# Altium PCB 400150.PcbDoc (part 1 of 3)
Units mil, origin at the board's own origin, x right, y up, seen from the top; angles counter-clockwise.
Board outline 4000 x 2500 mil, 4 copper layers (Top Layer, Mid-Layer 1, Mid-Layer 2, Bottom Layer), stack 62.293 mil thick; 200 components, 153 nets, 913 pads, 613 vias.
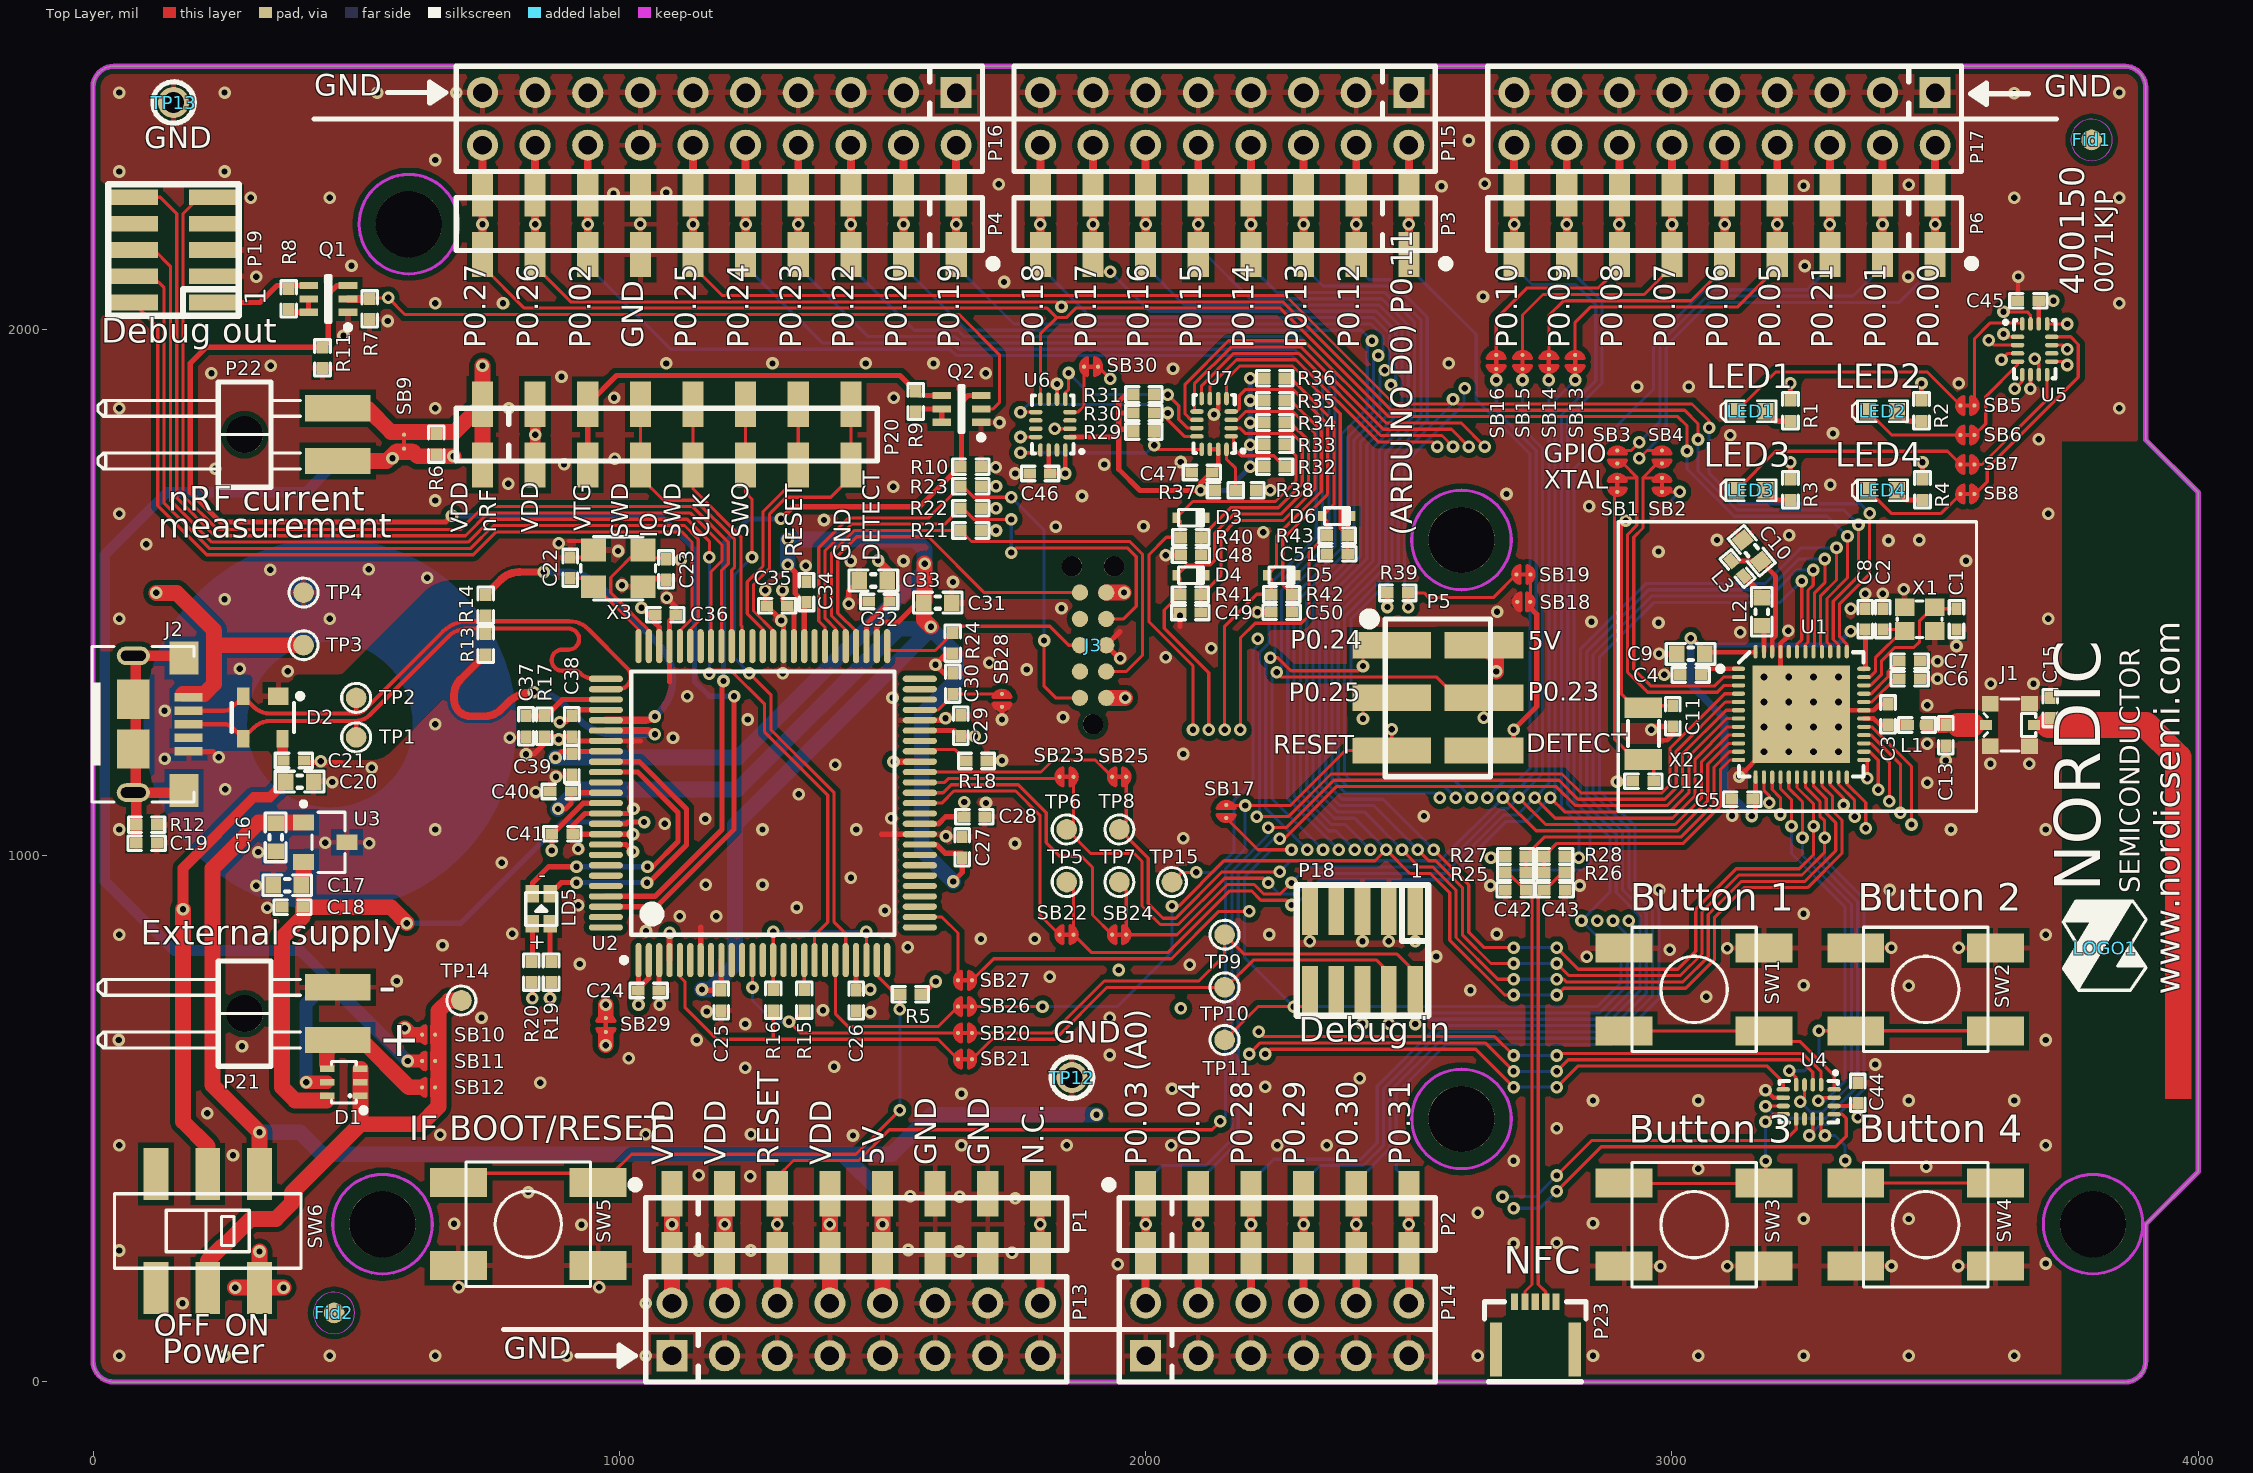
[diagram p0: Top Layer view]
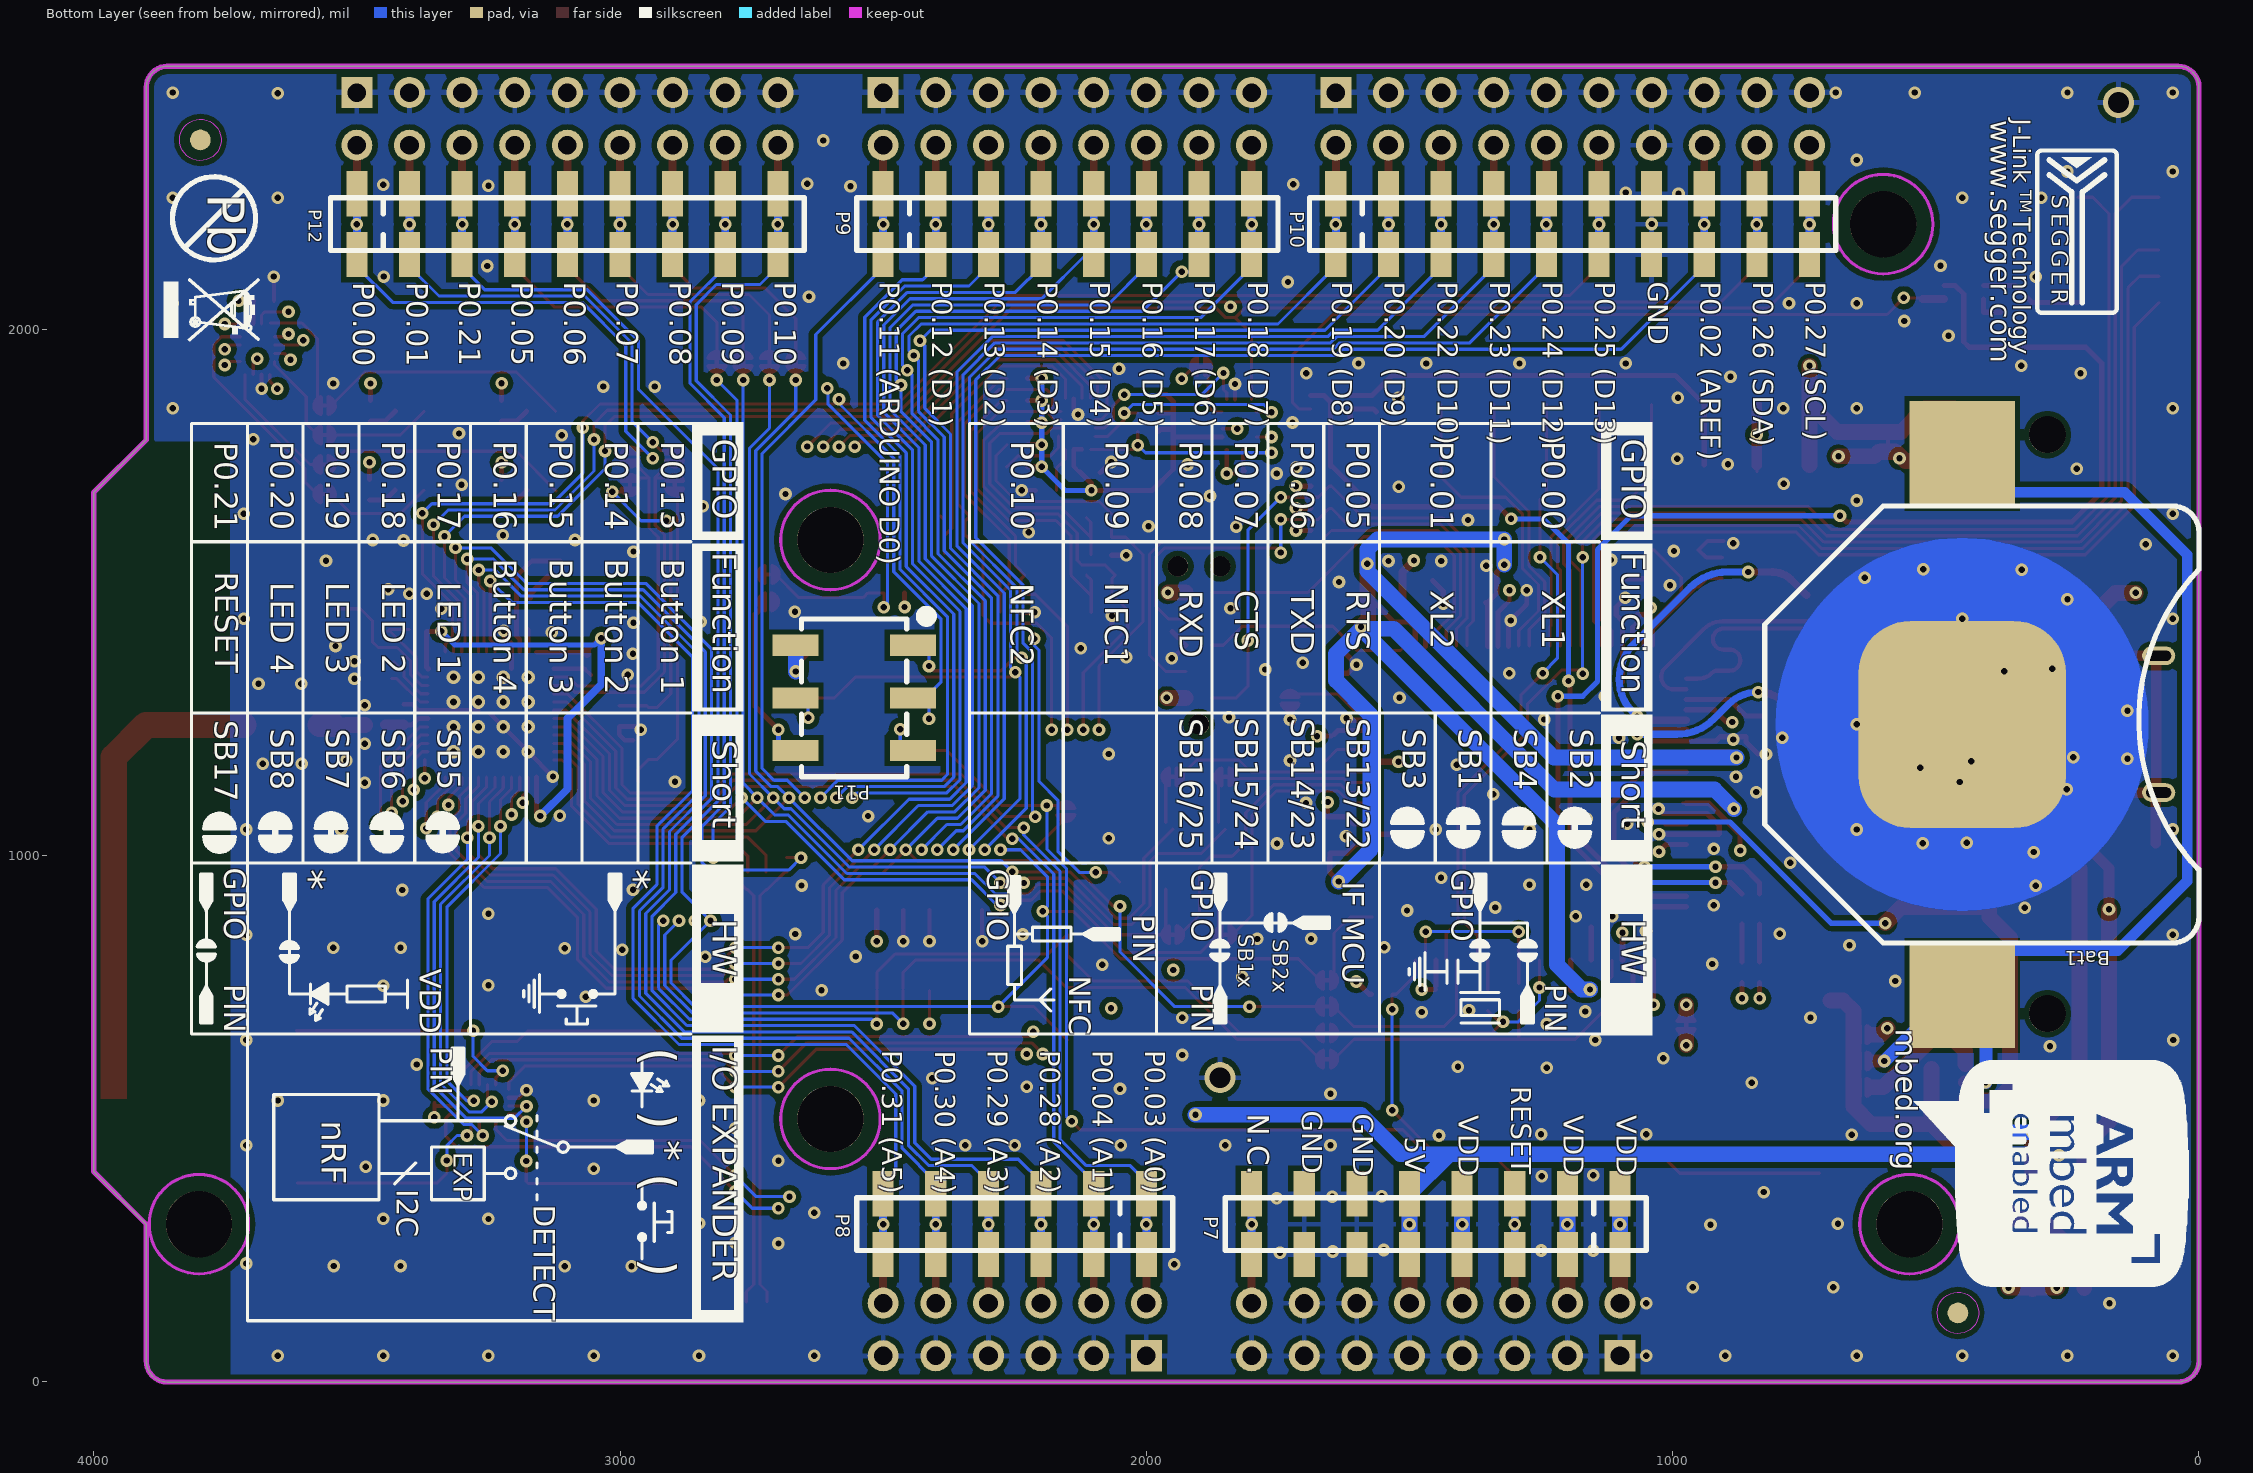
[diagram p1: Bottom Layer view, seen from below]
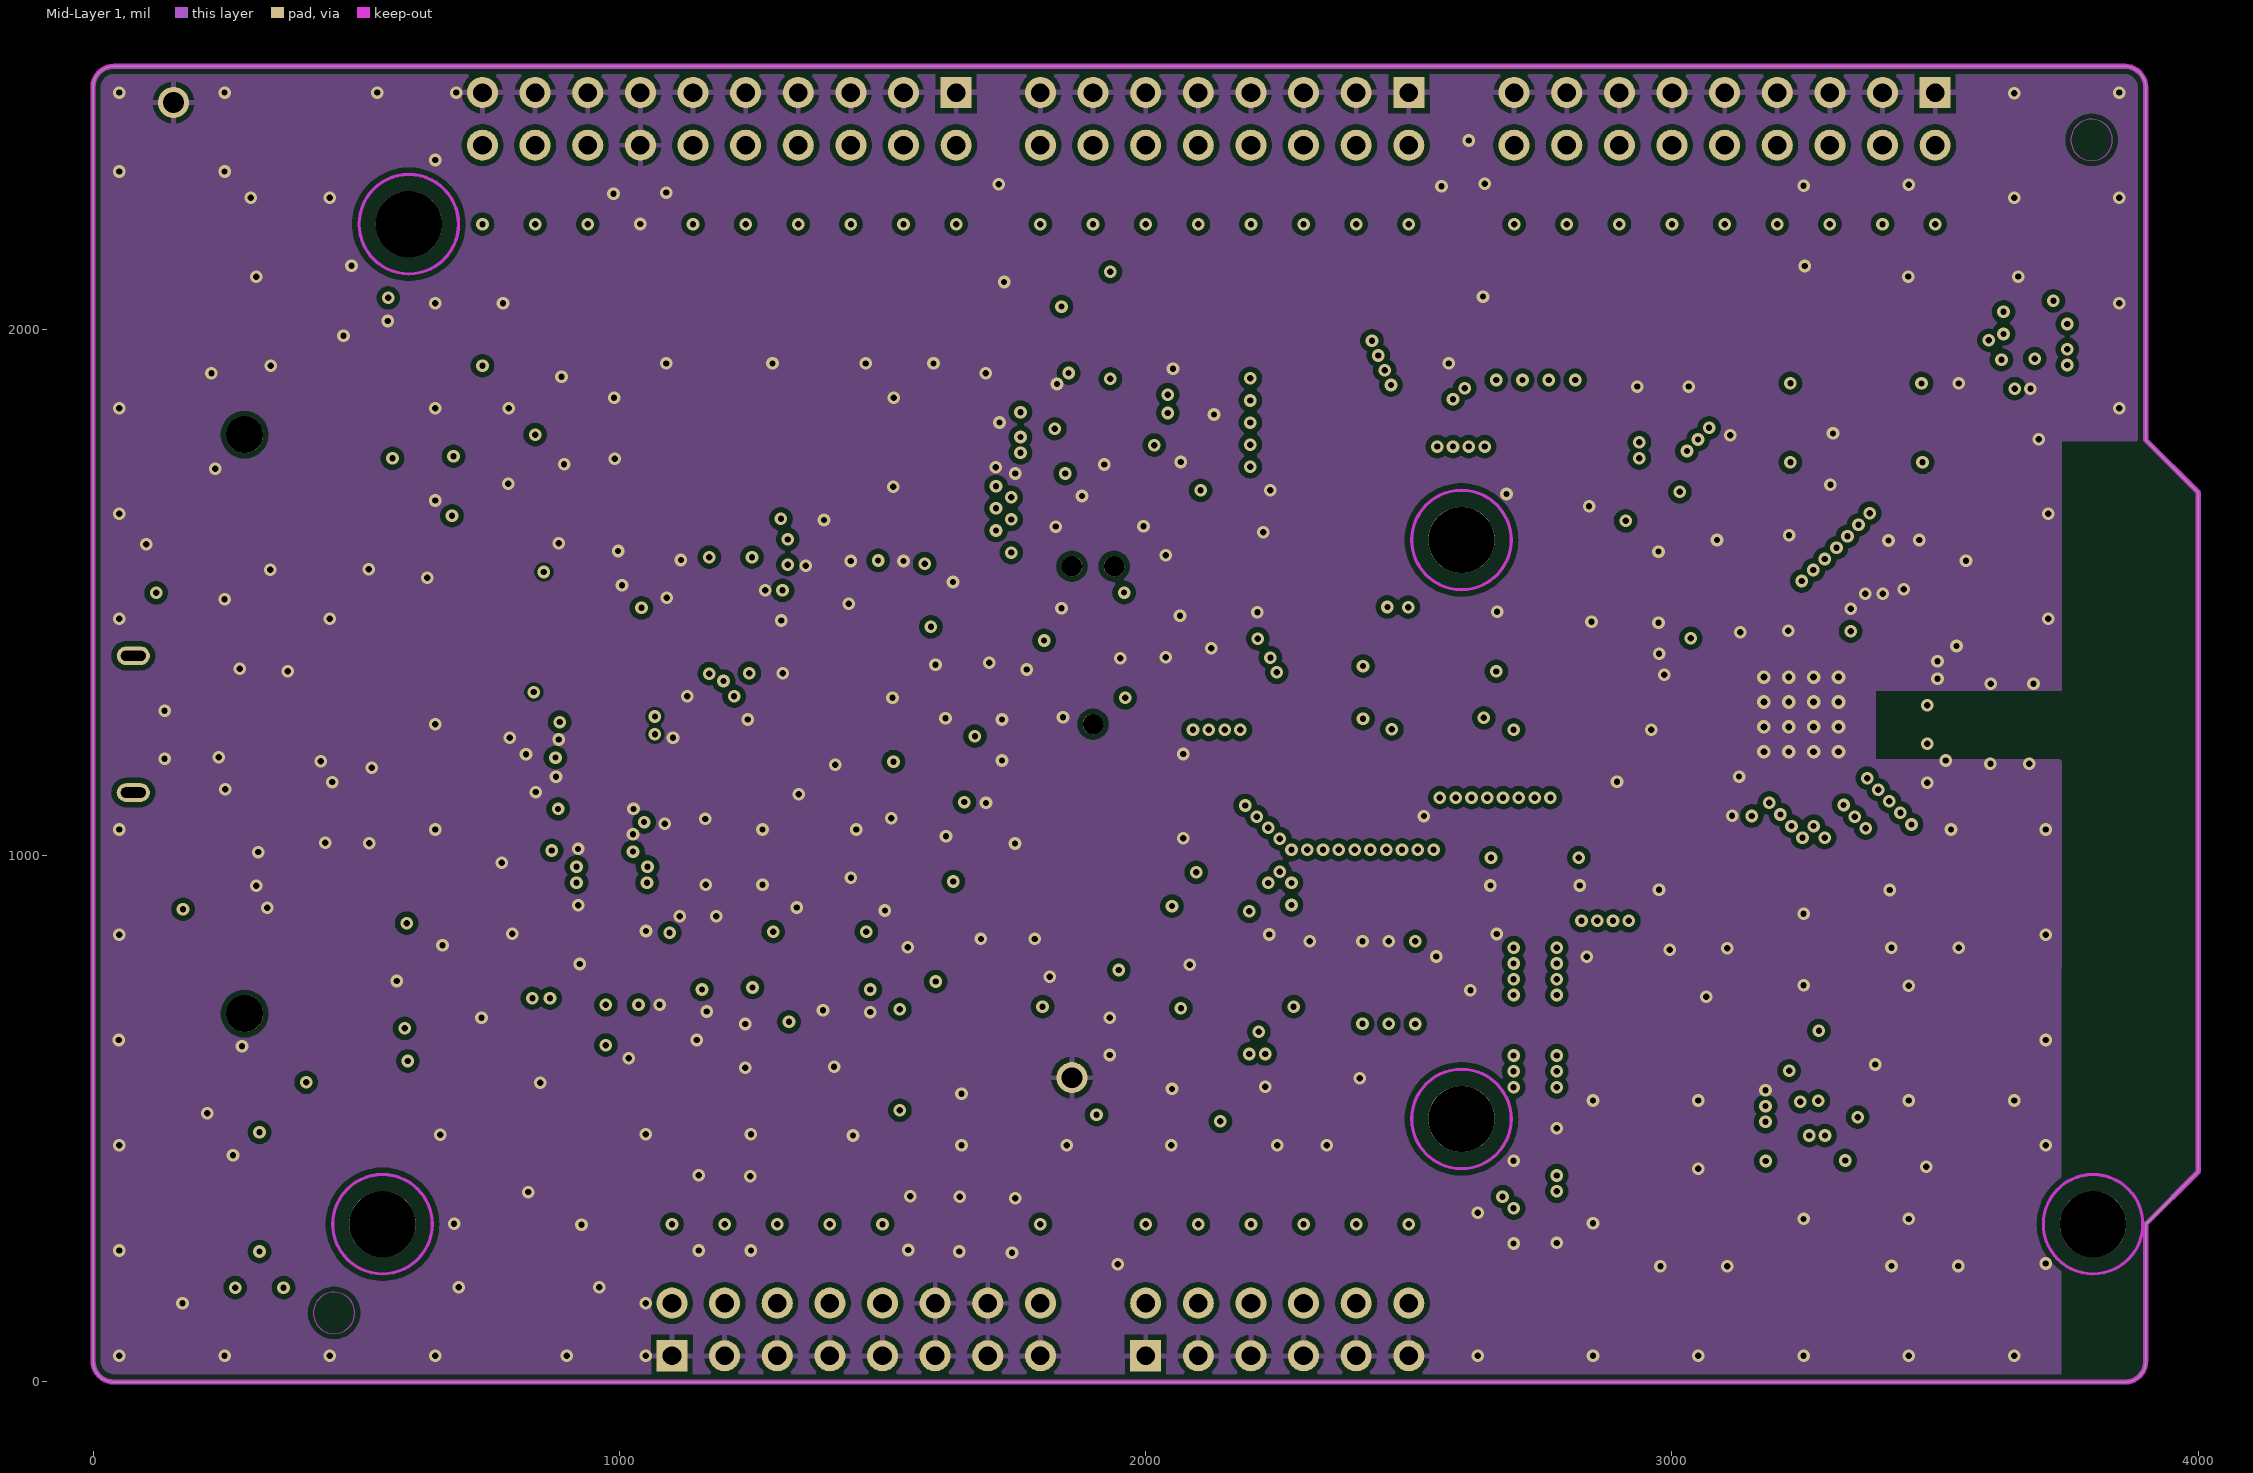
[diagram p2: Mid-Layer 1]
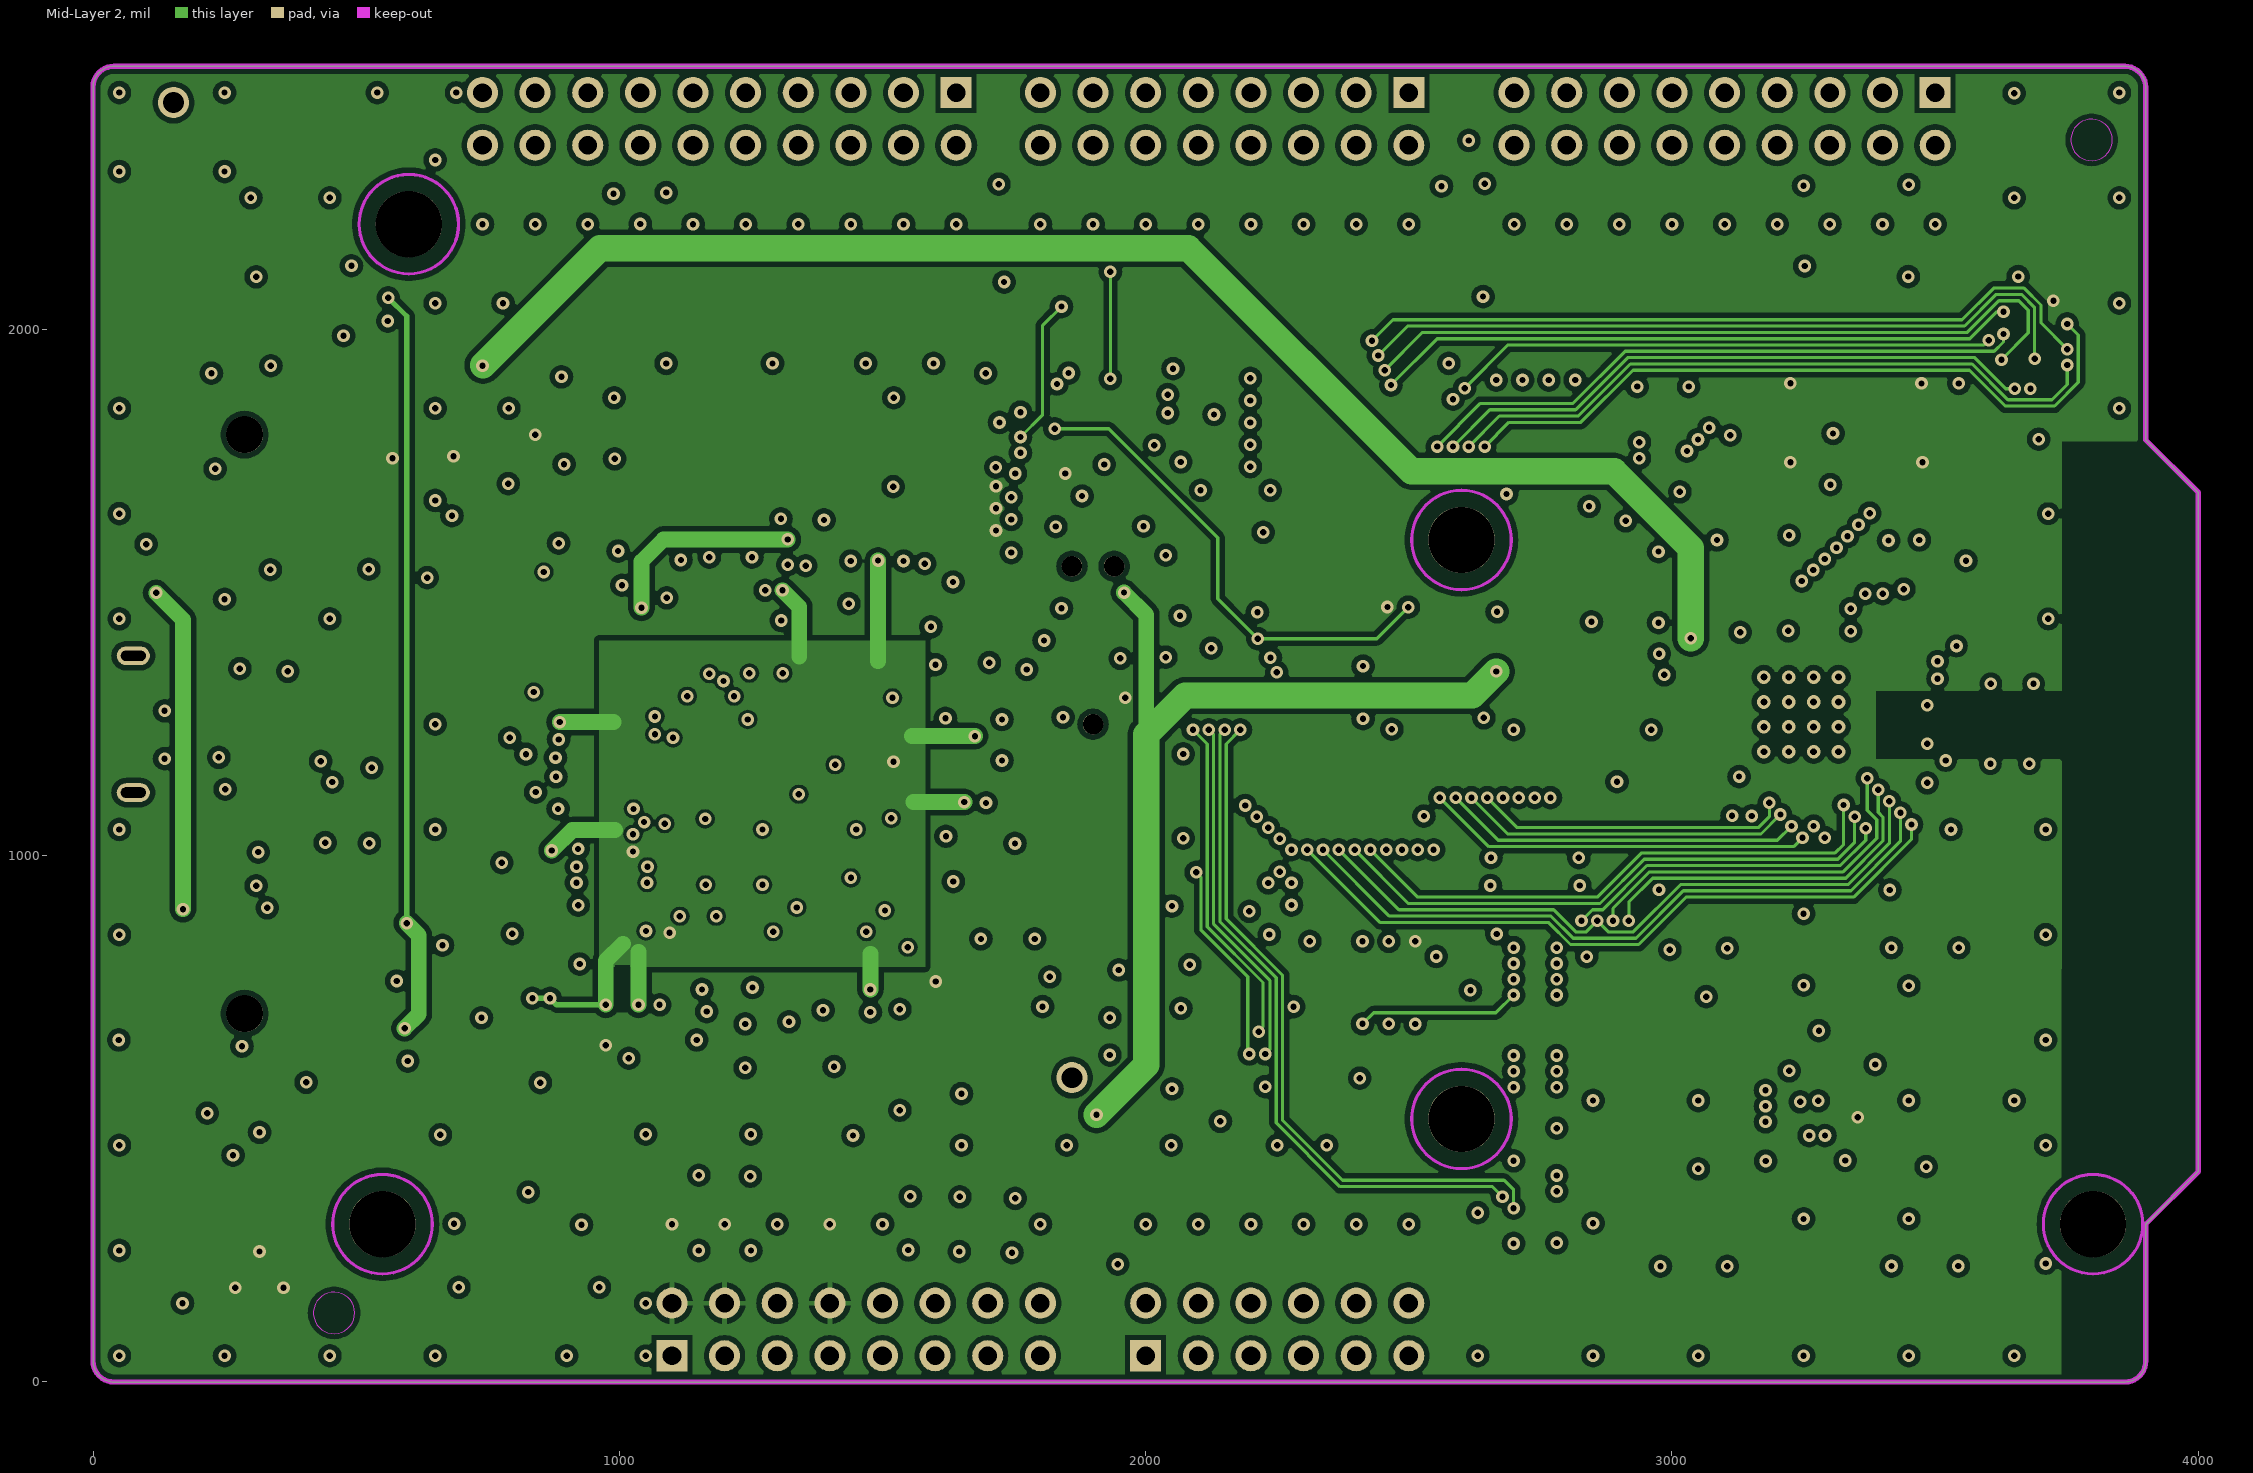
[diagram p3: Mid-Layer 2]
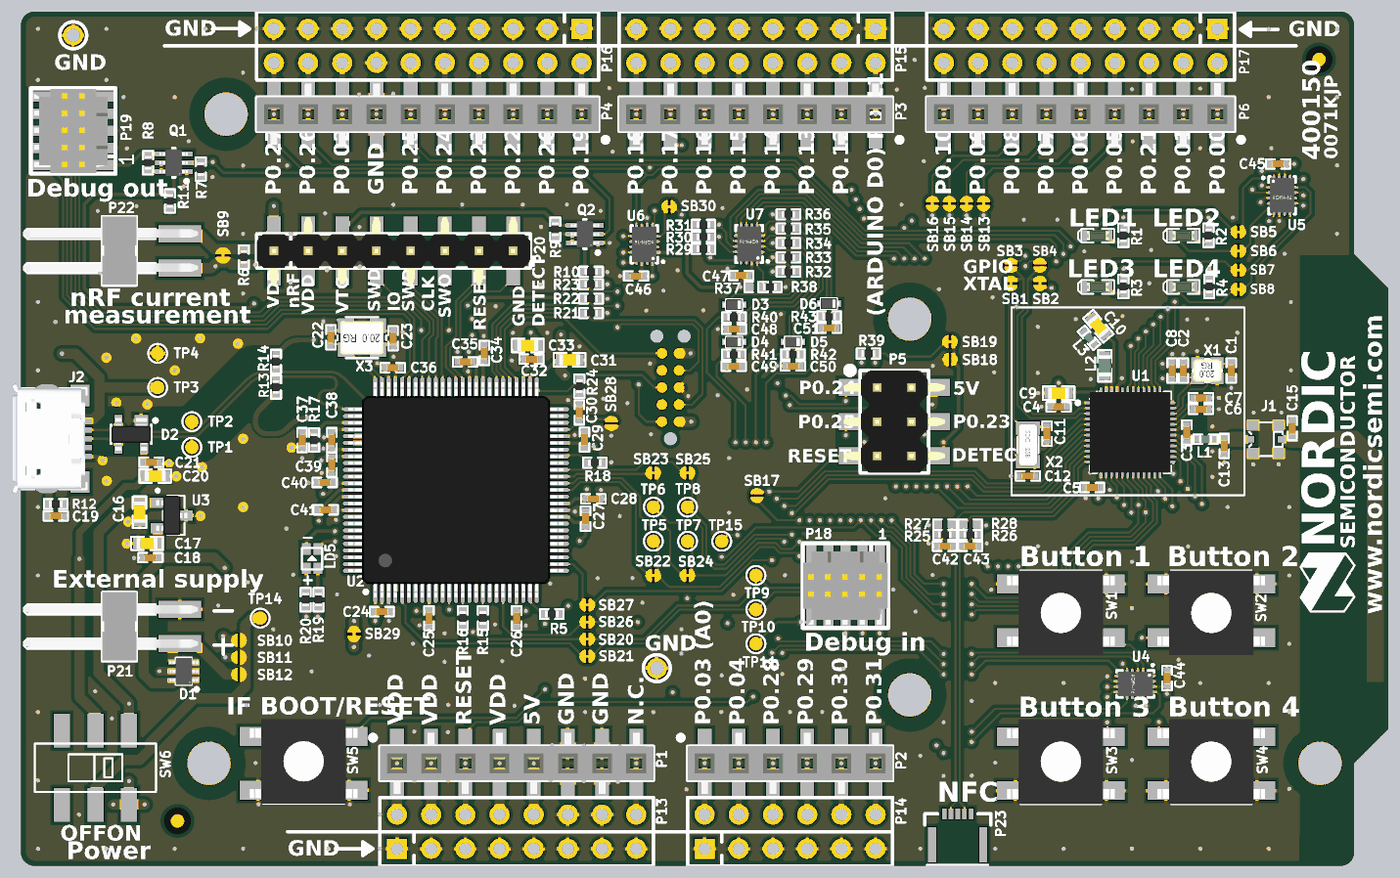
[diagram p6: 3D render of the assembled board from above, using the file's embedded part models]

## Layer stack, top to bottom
Top Solder: solder mask 0.4, Solder Resist, Dk 3.5
Top Layer: signal copper 1.4
Dielectric1: prepreg 7.0866, FR-4, Dk 4.4
Mid-Layer 1: signal copper 1.4
Dielectric2: core 42.5197, FR-4, Dk 4.4
Mid-Layer 2: signal copper 1.4
Dielectric3: prepreg 7.0866, FR-4, Dk 4.4
Bottom Layer: signal copper 1.4
Bottom Solder: solder mask 0.4, Solder Resist, Dk 3.5

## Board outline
0,39.6 0,2460.6 cw(c39.5,2460.1) 40,2499.6 3860,2499.6 cw(c3860,2459.6) 3900,2459.6 3900,1789.6 4000,1689.6 4000,399.6 3900,299.6 3900,39.6 cw(c3860.5,39.1) 3861,-0.4 40,-0.4 cw(c40,39.6)

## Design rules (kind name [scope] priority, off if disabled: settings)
Clearance USB_Poly_Clearance [(InNamedPolygon('Top_Layer-GND')) vs (OnLayer('Mechanical 3'))] p1: gap=10
Clearance USB_Clearance [(InDifferentialPairClass('All Differential Pairs'))] p2: gap=6
Clearance ANT_Clerance [InNet('ANT') or InNet('RF')] p3: gap=8
Clearance Polygon_Clearance [(InNamedPolygon('Top_Layer-GND')) or (InNamedPolygon('Bottom_Layer-GND')) or (InNamedPolygon('Mid_Layer_1-GND')) or (InNamedPolygon('Mid_Layer_2-VDD'))] p4: gap=10
Clearance SB_Clearance [HasFootprint('Solderbridge') or HasFootprint('QFN40P180X140X55-10N')] p5: gap=5
Clearance CSP_Clearance [HasFootprint('BGA4C40P2X2_76X76X62')] p6: gap=5
Clearance P23_Clearance [HasFootprint('Molex 051281-0594')] p7: gap=5
Clearance [All] p8: gap=6
ComponentClearance [All] p1 off: gap=10 collisioncheckmode=3 verticalgap=10 showdistances=FALSE
DiffPairsRouting [All] p1: maxlimit=10 minlimit=5.91 mostfreqgap=10 toplayer_maxgap=5.91 toplayer_prefgap=5.91 toplayer_minwidth=8 toplayer_maxwidth=15 toplayer_prefwidth=15 midlayer1_mingap=10 midlayer1_minwidth=8 midlayer1_maxwidth=15 midlayer1_prefwidth=15 midlayer2_mingap=10 midlayer2_minwidth=8 midlayer2_maxwidth=15 midlayer2_prefwidth=15 bottomlayer_maxgap=5.91 bottomlayer_prefgap=5.91 bottomlayer_minwidth=8 bottomlayer_maxwidth=15 bottomlayer_prefwidth=15 maxuncoupledlength=500
FabricationTestPointUsage TestPointUsage [All] p1: valid=0 allowmultiple=FALSE
FabricationTestpoint Testpoint [All] p1: side=3 testpointundercomponent=TRUE minsize=40 maxsize=100 preferedsize=60 minholesize=0 maxholesize=40 preferedholesize=32 testpointgrid=1 allowsidetop=TRUE allowsidebottom=TRUE usegrid=TRUE gridtolerance=0.01
Height [All] p1 off: minheight=0 maxheight=1000 prefheight=500
HoleSize [All] p1: absolutevalues=TRUE maxlimit=196.85 minlimit=12 maxpercent=80.000 minpercent=20.000
MinimumAnnularRing [All] p1 off: minimumring=6
PolygonConnect PolygonConnect_1 [isVia and innet(gnd) or isVia and innet('VDD') or HasFootprint('COAXIAL-SWF') or isVia and innet('VDD_SAM')] p1: connectstyle=Direct reliefconductorwidth=10 reliefentries=4 polygonreliefangle="90 Angle" airgapwidth=10
PolygonConnect [All] p2: connectstyle=Relief reliefconductorwidth=10 reliefentries=4 polygonreliefangle="90 Angle" airgapwidth=10
RoutingVias [All] p1: holewidth=12 width=24 viastyle="Through Hole" minholewidth=12 minwidth=24 maxholewidth=28 maxwidth=50
SilkToSolderMaskClearance SilkscreenOverComponentPads [IsPad] p1: minsilkscreentomaskgap=10 clearancetoexposedcopper=TRUE
SolderMaskExpansion [All] p1: expansion=3
Width [All] p1: maxlimit=400 minlimit=6 preferedwidth=6 minimp=50.000000 maximp=50.000000 favimp=50.000000
23 further rules are at their usual default settings.

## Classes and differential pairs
component class pca10040_sheet0_cover: Fid1 Fid2 LOGO1
component class pca10040_sheet1_radio: C1 C2 C3 C4 C5 C6 C7 C8 C9 C10 C11 C12 C13 C15 C42 C43 J1 L1 L2 L3 P23 R25 R26 R27 R28 SB1 SB2 SB3 SB4 U1 X1 X2
component class pca10040_sheet5_power_supply: Bat1 C16 C17 C18 D1 P21 P22 R6 SB9 SB10 SB11 SB12 SW6 TP12 TP13 TP14 U3
component class pca10040_sheet2_interface_mcu: C22 C23 C24 C25 C26 C27 C28 C29 C30 C31 C32 C33 C34 C35 C36 C37 C38 C39 C40 C41 LD5 Q1 Q2 R7 R8 R9 R10 R11 R15 R16 R17 R18 R19 R20 SB20 SB21 SB22 SB23 SB24 SB25 SB26 SB27 SB28 SB29 TP5 TP6 TP7 TP8 TP9 TP10 TP11 U2 X3
component class pca10040_sheet4_connectors: C19 C20 C21 D2 J2 J3 P1 P2 P3 P4 P5 P6 P7 P8 P9 P10 P11 P12 P13 P14 P15 P16 P17 P18 P19 P20 R12 R13 R14 R21 R22 R23 R24 R39 SB13 SB14 SB15 SB16 SB17 SB18 SB19 TP1 TP2 TP3 TP4 TP15
component class pca10040_sheet3_buttons_and_leds: C44 C45 C46 C47 C48 C49 C50 C51 D3 D4 D5 D6 LED1 LED2 LED3 LED4 R1 R2 R3 R4 R5 R29 R30 R31 R32 R33 R34 R35 R36 R37 R38 R40 R41 R42 R43 SB5 SB6 SB7 SB8 SB30 SW1 SW2 SW3 SW4 SW5 U4 U5 U6 U7
differential pair DHSD: +DHSD_P -DHSD_N
differential pair DFSD: +DFSD_P -DFSD_N

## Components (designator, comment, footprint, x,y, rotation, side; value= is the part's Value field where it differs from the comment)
Bat1 "Bat Holder CR2032" CR2032_HOLDER_SMD 450,1249 r270 bottom
C1 "12pF" CAPC1005X04L 3540.46,1449.16 r270 top (schematic designator C7)
C2 "12pF" CAPC1005X04L 3400.46,1449.16 r90 top
C3 "0.8pF" CAPC1005X04L 3410.46,1268.16 r270 top (schematic designator C20)
C4 "100nF" CAPC1005X04L 3035.46,1343.16 r180 top (schematic designator C5)
C5 "100nF" CAPC1005X04L 3133.46,1107.16 r180 top (schematic designator C6)
C6 "N.C." CAPC1005X04L 3451.46,1336.16 r0 top (schematic designator C8)
C7 "100pF" CAPC1005X04L 3451.46,1369.16 r0 top (schematic designator C11)
C8 "100nF" CAPC1005X04L 3367.46,1449.16 r90 top (schematic designator C12)
C9 "4.7µF" CAPC1608X06L 3035.46,1383.16 r180 top
C10 "1.0µF" CAPC1608X06L 3151.5,1579.16 r310 top (schematic designator C7)
C11 "12pF" CAPC1005X04L 3001.61,1264.85 r90 top
C12 "12pF" CAPC1005X04L 2945.61,1140.85 r0 top
C13 "N.C." CAPC1005X04L 3520,1228.6 r270 top
C15 "1.2pF" CAPC1005X04L 3718.87,1280.16 r90 top
C16 "1.0µF" CAPC1608X06L 347,1034.6 r90 top
C17 "1.0µF" CAPC1608X06L 369,943.6 r0 top
C18 "100nF" CAPC1005X04L 379,901.6 r0 top
C19 "100nF" CAPC1005X04L 101.84,1023.6 r180 top
C20 "10µF" CAPC1608X06L 392.61,1140.6 r180 top
C21 "100nF" CAPC1005X04L 381.61,1180.6 r180 top
C22 "18pF" CAPC1005X04L 906.61,1546.6 r90 top
C23 "18pF" CAPC1005X04L 1088.61,1543.6 r270 top
C24 "100nF" CAPC1005X04L 1055.61,743.6 r180 top
C25 "100nF" CAPC1005X04L 1193.61,724.6 r90 top
C26 "100nF" CAPC1005X04L 1450,724.6 r90 top
C27 "100nF" CAPC1005X04L 1651.61,1015.6 r270 top
C28 "100nF" CAPC1005X04L 1674.61,1073.6 r180 top
C29 "100nF" CAPC1005X04L 1648.61,1246.6 r270 top
C30 "10nF" CAPC1005X04L 1633.61,1326.6 r270 top
C31 "10µF" CAPC1608X06L 1605,1480.6 r180 top
C32 "100nF" CAPC1005X04L 1493.61,1482.6 r0 top
C33 "10µF" CAPC1608X06L 1482.61,1522.6 r0 top
C34 "100nF" CAPC1005X04L 1355.61,1500.6 r270 top
C35 "100nF" CAPC1005X04L 1299.61,1474.6 r0 top
C36 "100nF" CAPC1005X04L 1087.61,1457.6 r0 top
C37 "10pF" CAPC1005X04L 822.61,1245.6 r90 top
C38 "100nF" CAPC1005X04L 909.61,1245.6 r90 top
C39 "100nF" CAPC1005X04L 909.61,1173.6 r90 top
C40 "100nF" CAPC1005X04L 888.61,1121.6 r0 top
C41 "100nF" CAPC1005X04L 891.61,1041.6 r180 top
C42 "300pF" CAPC1005X04L 2703,935 r180 top
C43 "300pF" CAPC1005X04L 2777,935 r180 top
C44 "100nF" CAPC1005X04L 3352.66,549 r270 top
C45 "100nF" CAPC1005X04L 3677,2054 r0 top
C46 "100nF" CAPC1005X04L 1799.31,1725.77 r0 top
C47 "100nF" CAPC1005X04L 2106.99,1727.77 r0 top
C48 "1.0µF" CAPC1005X04L 2085.99,1570.77 r180 top
C49 "1.0µF" CAPC1005X04L 2085.08,1461.77 r0 top
C50 "1.0µF" CAPC1005X04L 2258.31,1462.47 r0 top
C51 "1.0µF" CAPC1005X04L 2364.08,1573.69 r180 top
D1 "SD103ATW-7-F" SOT-363 508,543.6 r90 top
D2 "PRTR5V0U2X" SOT190P230X110-4L 322.61,1262.6 r270 top
D3 "1PS79SB30.115" SOD-523 2086.22,1641.77 r180 top
D4 "1PS79SB30.115" SOD-523 2086.31,1532.77 r180 top
D5 "1PS79SB30.115" SOD-523 2258.31,1532.77 r180 top
D6 "1PS79SB30.115" SOD-523 2363.31,1645 r180 top
Fid1 "Fiducial mark" Fiducial 3797.28,2359.6 r180 top
Fid2 "Fiducial mark" Fiducial 458,131 r0 top
J1 "MM8130-2600" COAXIAL-SWF 3641.87,1248.16 r90 top
J2 "MicroUSB-B" FCI_10118193-0001LF 181.84,1249.6 r0 top
J3 "TC2050-IDC" TC2050-IDC-NLFP 1900,1399.6 r90 top
L1 "3.9nH" INDC1005X04L 3465.46,1248.16 r0 top (schematic designator L2)
L2 "10µH" INDC1608X06L 3170.46,1463.16 r270 top (schematic designator L4)
L3 "15nH" INDC1005X04L 3124.5,1545.16 r310 top (schematic designator L5)
LD5 "LTST-C195KGJRKT" LED_DUAL_0606 851.61,898.6 r180 top (schematic designator LD3)
LED1 "L0603G" LED_0603_G 3150,1843.99 r0 top
LED2 "L0603G" LED_0603_G 3400,1843.99 r0 top
LED3 "L0603G" LED_0603_G 3150,1693.99 r0 top
LED4 "L0603G" LED_0603_G 3400,1693.99 r0 top
LOGO1 "Nordic Logo M" NORDIC_LOGO_M 3822.92,823.93 r90 top
P1 "Socket 1x8" SOCKET_1x8_SMD 1100,299.6 r0 top locked (schematic designator P11)
P2 "Socket 1x6" SOCKET_1x6_SMD 2000,299.6 r0 top locked (schematic designator P12)
P3 "Socket 1x8" SOCKET_1x8_SMD 2500,2199.6 r180 top locked (schematic designator P8)
P4 "Socket 1x10" SOCKET_1x10_SMD 1640,2199.6 r180 top locked (schematic designator P9)
P5 "Pin Hdr 2x3" "Molex 15-91-2060" 2555,1299.6 r270 top locked (schematic designator P6)
P6 "Socket 1x9" SOCKET_1x9_SMD 3500,2199.6 r180 top locked
P7 "Pin List 1x8" LIST_1x8_SMD 1100,299.6 r0 bottom locked (schematic designator POWER)
P8 "Pin List 1x6" LIST_1x6_SMD 2000,299.6 r0 bottom locked (schematic designator AD)
P9 "Pin List 1x8" LIST_1x8_SMD 2500,2199.6 r180 bottom locked (schematic designator IOL)
P10 "Pin List 1x10" LIST_1x10_SMD 1640,2199.6 r180 bottom locked (schematic designator IOH)
P11 "Socket 2x3" SOCKET_2x3_SMD-2.54mm-bottom 2555,1299.6 r270 top locked (schematic designator ICSP)
P12 "Pin List 1x9" LIST_1x9_SMD 3500,2199.6 r180 bottom locked
P13 "Pin Header 2x8" HDR_2x8 1450,99.6 r0 top locked
P14 "Pin Header 2x6" HDR_2x6 2250,99.6 r0 top locked
P15 "Pin Header 2x8" HDR_2x8 2150,2399.6 r180 top locked
P16 "Pin Header 2x10" HDR_2x10 1190,2399.6 r180 top locked
P17 "Pin Header 2x9" HDR_2x9 3100,2399.6 r180 top
P18 "FTSH-105" FTSH-105-K 2412,819.77 r180 top
P19 "FTSH-105" FTSH-105-K 153,2150.6 r90 top locked
P20 "Pin List 1x8" LIST_1x8_SMD 740,1799.6 r0 top
P21 "Pin List 1x2, Angled" LIST_ANG_1x2-SMD-2.54MM 465,699.6 r270 top
P22 "Pin List 1x2, Angled" LIST_ANG_1x2-SMD-2.54MM 465,1799.6 r270 top
P23 "Molex 051281-0594" "Molex 051281-0594" 2701,152 r0 top
Q1 "FDG6321C" SOT65P210X100-6N 447,2057.6 r180 top
Q2 "FDG6321C" SOT65P210X100-6N 1650,1848.6 r180 top
R1 "220R" RESC1005X04L 3225.01,1844.99 r90 top
R2 "220R" RESC1005X04L 3474.01,1844.99 r90 top
R3 "220R" RESC1005X04L 3225.01,1694.99 r90 top
R4 "220R" RESC1005X04L 3476.01,1694.99 r90 top
R5 "10k" RESC1005X04L 1553,736.6 r0 top
R6 "N.C." RESC1005X04L 652,1781.6 r90 top
R7 "47k" RESC1005X04L 526,2038.6 r270 top
R8 "10k" RESC1005X04L 372,2057.6 r270 top
R9 "10k" RESC1005X04L 1563,1862.6 r270 top
R10 "10k" RESC1005X04L 1667.84,1738.6 r180 top
R11 "10k" RESC1005X04L 436,1945.6 r90 top
R12 "10k" RESC1005X04L 101.84,1058.6 r180 top
R13 "39R" RESC1005X04L 746.02,1401.3 r90 top
R14 "39R" RESC1005X04L 746.01,1475.54 r270 top
R15 "150R" RESC1005X04L 1351.35,725 r270 top
R16 "150R" RESC1005X04L 1292.35,725 r270 top
R17 "6k8" RESC1005X04L 857.61,1245.6 r90 top
R18 "1k" RESC1005X04L 1678.61,1179.6 r180 top
R19 "220R" RESC1005X04L 870.34,778.6 r270 top
R20 "220R" RESC1005X04L 832.87,778.6 r270 top
R21 "4k7" RESC1005X04L 1667.84,1617.6 r0 top
R22 "4k7" RESC1005X04L 1667.84,1659.6 r0 top
R23 "4k7" RESC1005X04L 1667.84,1701.6 r0 top
R24 "4k7" RESC1005X04L 1633.61,1403.6 r270 top
R25 "0R" RESC1005X04L 2702.84,968.6 r0 top
R26 "0R" RESC1005X04L 2776.84,968.6 r180 top
R27 "N.C." RESC1005X04L 2702.84,998.6 r0 top
R28 "N.C." RESC1005X04L 2776.84,998.6 r180 top
R29 "4k7" RESC1005X04L 1996.62,1805.77 r180 top
R30 "4k7" RESC1005X04L 1996.62,1840.77 r180 top
R31 "12k" RESC1005X04L 1996.62,1875.77 r180 top
R32 "12k" RESC1005X04L 2244.94,1738.62 r180 top
R33 "100k" RESC1005X04L 2244.94,1780.62 r180 top
R34 "100k" RESC1005X04L 2244.94,1822.62 r180 top
R35 "100k" RESC1005X04L 2244.94,1864.62 r180 top
R36 "100k" RESC1005X04L 2244.94,1906.62 r180 top
R37 "N.C." RESC1005X04L 2151.31,1693.77 r180 top
R38 "0R" RESC1005X04L 2190.68,1693.77 r180 top
R39 "1M0" RESC1005X04L 2479,1499 r180 top
R40 "18k" RESC1005X04L 2085.99,1604.77 r180 top
R41 "18k" RESC1005X04L 2085.08,1495.77 r180 top
R42 "18k" RESC1005X04L 2258.31,1496.47 r180 top
R43 "18k" RESC1005X04L 2364.08,1607.69 r180 top
SB1 "Solderbridge" Solderbridge_Shorted 2896,1691 r90 top net-tie
SB2 "Solderbridge" Solderbridge_Shorted 2981,1691 r90 top net-tie
SB3 "Solderbridge" Solderbridge#1 2896,1745 r90 top
SB4 "Solderbridge" Solderbridge#1 2981,1745 r90 top
SB5 "Solderbridge" Solderbridge_Shorted 3574.5,1855 r180 top net-tie (schematic designator SB6)
SB6 "Solderbridge" Solderbridge_Shorted 3574.5,1799 r180 top net-tie
SB7 "Solderbridge" Solderbridge_Shorted 3574.5,1743 r180 top net-tie
SB8 "Solderbridge" Solderbridge_Shorted 3574.5,1687 r180 top net-tie
SB9 "Solderbridge" Solderbridge_Shorted 591,1799.6 r270 top net-tie
SB10 "Solderbridge" Solderbridge#1 650,659.6 r180 top
SB11 "Solderbridge" Solderbridge#1 650,609.6 r180 top
SB12 "Solderbridge" Solderbridge#1 650,559.6 r180 top
SB13 "Solderbridge" Solderbridge_Shorted 2816,1951 r270 top net-tie
SB14 "Solderbridge" Solderbridge_Shorted 2766,1951 r270 top net-tie
SB15 "Solderbridge" Solderbridge_Shorted 2716,1951 r270 top net-tie
SB16 "Solderbridge" Solderbridge_Shorted 2666,1951 r270 top net-tie
SB17 "Solderbridge" Solderbridge#2 2153,1096 r270 top
SB18 "Solderbridge" Solderbridge#2 2706,1482 r0 top
SB19 "Solderbridge" Solderbridge_Shorted 2731,1534 r180 top net-tie
SB20 "Solderbridge" Solderbridge_Shorted 1670.02,663 r180 top net-tie
SB21 "Solderbridge" Solderbridge_Shorted 1670.02,613 r180 top net-tie
SB22 "Solderbridge" Solderbridge_Shorted 1863,849.6 r180 top net-tie
SB23 "Solderbridge" Solderbridge_Shorted 1863,1149.6 r180 top net-tie
SB24 "Solderbridge" Solderbridge_Shorted 1963,849.6 r180 top net-tie
SB25 "Solderbridge" Solderbridge_Shorted 1963,1149.6 r180 top net-tie
SB26 "Solderbridge" Solderbridge_Shorted 1670.02,713 r180 top net-tie
SB27 "Solderbridge" Solderbridge_Shorted 1670.02,763 r180 top net-tie
SB28 "Solderbridge" Solderbridge#3 1727,1307.09 r270 top
SB29 "Solderbridge" Solderbridge_Shorted 974.38,691.38 r270 top net-tie
SB30 "Solderbridge" Solderbridge_Shorted 1909.52,1928.77 r180 top net-tie
SW1 "PB SW" ALPS_SKHUxxx010_WO_GND 3042,745.66 r180 top
SW2 "PB SW" ALPS_SKHUxxx010_WO_GND 3482,745.66 r180 top
SW3 "PB SW" ALPS_SKHUxxx010_WO_GND 3042,298.66 r0 top
SW4 "PB SW" ALPS_SKHUxxx010_WO_GND 3482,298.66 r0 top
SW5 "PB SW" ALPS_SKHUxxx010_WO_GND 827,299.6 r0 top
SW6 "Switch" JS202011SCQN 218,286.6 r0 top
TP1 "Ø1.0mm,SMD" TP_SMD_Ø1.0mm 500,1224.6 r0 top
TP2 "Ø1.0mm,SMD" TP_SMD_Ø1.0mm 500,1299.6 r0 top
TP3 "Ø1.0mm,SMD" TP_SMD_Ø1.0mm 400,1399.6 r0 top
TP4 "Ø1.0mm,SMD" TP_SMD_Ø1.0mm 400,1499.6 r0 top
TP5 "Ø1.0mm,SMD" TP_SMD_Ø1.0mm 1850,949.6 r0 top
TP6 "Ø1.0mm,SMD" TP_SMD_Ø1.0mm 1850,1049.6 r0 top
TP7 "Ø1.0mm,SMD" TP_SMD_Ø1.0mm 1950,949.6 r0 top
TP8 "Ø1.0mm,SMD" TP_SMD_Ø1.0mm 1950,1049.6 r0 top
TP9 "Ø1.0mm,SMD" TP_SMD_Ø1.0mm 2150,849.6 r0 top
TP10 "Ø1.0mm,SMD" TP_SMD_Ø1.0mm 2150,749.6 r0 top
TP11 "Ø1.0mm,SMD" TP_SMD_Ø1.0mm 2150,649.6 r90 top
TP12 "TP" TESTPAD-TH 1860,578 r0 top
TP13 "TP" TESTPAD-TH 153,2430.6 r0 top
TP14 "Ø1.0mm,SMD" TP_SMD_Ø1.0mm 700,724.6 r270 top
TP15 "Ø1.0mm,SMD" TP_SMD_Ø1.0mm 2050,949.6 r90 top
U1 "nRF52832-QFAA" QFN40P600X600X90-48N 3245.46,1268.16 r0 top
U2 "ATSAM3U2CA-AU" TSQFP50P1600X1600X160-100N 1272.61,1099.6 r90 top locked
U3 "AP7333-33SAG-7" SOT-23A 400,1062.6 r270 top
U4 "NX3DV2567" XQFN40P180X260X50-16N 3259.66,532 r270 top
U5 "NX3DV2567" XQFN40P180X260X50-16N 3689,1962 r0 top
U6 "NX3DV2567" XQFN40P180X260X50-16N 1823.62,1818.77 r180 top
U7 "PCAL6408A" XQFN40P180X260X50-16N 2129.94,1820 r180 top
X1 "32MHz" BT-XTAL_2016 3470.46,1449.16 r180 top
X2 "32.768kHz" XTAL_3215 2945.61,1231.85 r270 top
X3 "12MHz" BT-XTAL_3225 997.61,1545.6 r180 top

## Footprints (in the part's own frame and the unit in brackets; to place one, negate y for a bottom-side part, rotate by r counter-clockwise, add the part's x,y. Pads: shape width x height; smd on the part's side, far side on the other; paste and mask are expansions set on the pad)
ALPS_SKHUxxx010_WO_GND [mm] "6.2×6.5mm TACT Switch, without ground connector"
  rect 2.75x1.4 smd: 1(-3.375,2) 1(3.375,2) 2(-3.375,-2) 2(3.375,-2)
  silkscreen extent -3,-3 3,3, body extent -4,-3 4,3.3, height 3.1
BT-XTAL_2016 [mm] "Crystal 2.0 x 1.6 mm"
  rect 0.95x0.85 smd: 1(-0.725,-0.575) 2(0.725,-0.575) 3(0.725,0.575) 4(-0.725,0.575)
  silkscreen extent -1.08,-0.88 1.08,0.88, body extent -1.05,-0.85 1.05,0.85, height 0.56
BT-XTAL_3225 [mm] "Mercury X32 series"
  rect 1.2x1.1 smd: 1(-1.194,-0.89) 2(1.194,-0.89) 3(1.194,0.891) 4(-1.194,0.891)
  silkscreen extent -1.8,-1.52 1.8,1.52, body extent -1.6,-1.25 1.61,1.25, height 0.81
CAPC1005X04L [mm] "Chip Capacitor, 2-Leads, Body 1.0x0.5mm, IPC High Density"
  rect 0.6x0.5 smd: 1(-0.5,0) 2(0.5,0)
  silkscreen extent -0.9,-0.35 0.9,0.35, body extent -0.51,-0.25 0.51,0.25, height 0.5
CAPC1608X06L [mm] "Chip Capacitor, 2-Leads, Body 1.6x0.8mm, IPC High Density"
  rect 0.75x0.8 smd: 1(-0.675,0) 2(0.675,0)
  silkscreen extent -1.17,-0.5 1.17,0.5, body extent -0.8,-0.43 0.8,0.43, height 0.8
COAXIAL-SWF [mm]
  rect 0.5x0.58 smd: 1(0,1.16) 3(0,-1.16)
  rect 0.75x0.8 smd: 2(-1.025,-0.95) 2(-1.025,0.95) 2(1.025,-0.95) 2(1.025,0.95)
  Top Layer pour cut-out: -0.65,0.55 0.65,0.55 0.65,1.35 -0.65,1.35
  Top Layer pour cut-out: 0.65,-0.55 -0.65,-0.55 -0.65,-1.35 0.65,-1.35
  silkscreen extent -1.25,-1.25 1.25,1.25
CR2032_HOLDER_SMD [mm] "CR2032 - SMD mount coin cell bat holder"
  round 18 on Bottom Solder paste+0: 0(0,0)
  rect 5.08x5.08 smd: 1(-13.081,0) 1(13.081,0)
  rrect50% 10x10 smd paste-9: 2(0,0)
  Top Layer circle w5: c0,0 r6.5
  silkscreen extent -10.54,-9.53 10.54,11.43, body extent -15.37,-10.27 15.37,9.78, height 3.96
FCI_10118193-0001LF [mm] "Micro USB B SMT"
  rect 1.35x0.4 smd: 1(0,1.3) 2(0,0.65) 3(0,0) 4(0,-0.65) 5(0,-1.3)
  oval 1.6x0.9 hole 0.5 slot 1.2 at 0 deg: 6(-2.675,-3.3) 6(-2.675,3.3)
  oval 2x1.5 on Top Paste: 6(-2.675,-3.3) 6(-2.675,3.3)
  rect 1.55x1.9 smd: 6(-2.675,-1.2) 6(-2.675,1.2)
  rect 1.4x1.6 smd: 6(-0.225,-3.2) 6(-0.225,3.2)
  silkscreen extent -4.75,-3.75 0.25,3.75, body extent -5.28,-4.1 0.15,4.1, height 2.72
Fiducial [mm] "Fiducial Mark"
  round 1 smd paste-10 mask+0.5: 0(0,0)
  round 1 smd far side paste-10 mask+0.5: 0(0,0)
  Keep-Out Layer circle w0.01: c0,0 r1
FTSH-105-K [mm] "SMT MICRO HEADER, (1,27) .050\" Keying Shroud"
  rect 0.76x2.4 smd: 1(-2.54,-1.95) 2(-2.54,1.95) 3(-1.27,-1.95) 4(-1.27,1.95) 5(0,-1.95) 6(0,1.95) 7(1.27,-1.95) 8(1.27,1.95) 9(2.54,-1.95) 10(2.54,1.95)
  silkscreen extent -3.18,-3.15 3.18,3.15, body extent -3.14,-2.92 3.14,2.92, height 5.71
HDR_2x6 [mm] "Pin Header, 2.54mm through hole"
  rect 1.5x1.5 hole 0.9: 1(-6.35,-1.27)
  round 1.5 hole 0.9: 2(-6.35,1.27) 3(-3.81,-1.27) 4(-3.81,1.27) 5(-1.27,-1.27) 6(-1.27,1.27) 7(1.27,-1.27) 8(1.27,1.27) 9(3.81,-1.27) 10(3.81,1.27) 11(6.35,-1.27) 12(6.35,1.27)
  silkscreen extent -7.62,-2.54 7.62,2.54
HDR_2x8 [mm] "Pin Header, 2.54mm through hole"
  rect 1.5x1.5 hole 0.9: 1(-8.89,-1.27)
  round 1.5 hole 0.9: 2(-8.89,1.27) 3(-6.35,-1.27) 4(-6.35,1.27) 5(-3.81,-1.27) 6(-3.81,1.27) 7(-1.27,-1.27) 8(-1.27,1.27) 9(1.27,-1.27) 10(1.27,1.27) 11(3.81,-1.27) 12(3.81,1.27) 13(6.35,-1.27) 14(6.35,1.27) 15(8.89,-1.27) 16(8.89,1.27)
  silkscreen extent -10.16,-2.54 10.16,2.54
HDR_2x9 [mm] "Pin Header, 2.54mm through hole"
  rect 1.5x1.5 hole 0.9: 1(-10.16,-1.27)
  round 1.5 hole 0.9: 2(-10.16,1.27) 3(-7.62,-1.27) 4(-7.62,1.27) 5(-5.08,-1.27) 6(-5.08,1.27) 7(-2.54,-1.27) 8(-2.54,1.27) 9(0,-1.27) 10(0,1.27) 11(2.54,-1.27) 12(2.54,1.27) 13(5.08,-1.27) 14(5.08,1.27) 15(7.62,-1.27) 16(7.62,1.27) 17(10.16,-1.27) 18(10.16,1.27)
  silkscreen extent -11.43,-2.54 11.43,2.54
HDR_2x10 [mm] "Pin Header, 2.54mm through hole"
  rect 1.5x1.5 hole 0.9: 1(-11.43,-1.27)
  round 1.5 hole 0.9: 2(-11.43,1.27) 3(-8.89,-1.27) 4(-8.89,1.27) 5(-6.35,-1.27) 6(-6.35,1.27) 7(-3.81,-1.27) 8(-3.81,1.27) 9(-1.27,-1.27) 10(-1.27,1.27) 11(1.27,-1.27) 12(1.27,1.27) 13(3.81,-1.27) 14(3.81,1.27) 15(6.35,-1.27) 16(6.35,1.27) 17(8.89,-1.27) 18(8.89,1.27) 19(11.43,-1.27) 20(11.43,1.27)
  silkscreen extent -12.7,-2.54 12.7,2.54
INDC1005X04L [mm] "Chip Inductor, 2-Leads, Body 1.0x0.5mm, IPC High Density"
  rect 0.65x0.5 smd: 1(-0.475,0) 2(0.475,0)
  silkscreen extent -0.9,-0.35 0.9,0.35, body extent -0.5,-0.3 0.5,0.3, height 0.5
INDC1608X06L [mm] "Chip Inductor, 2-Leads, Body 1.6x0.8mm, IPC High Density"
  rect 0.75x0.8 smd: 1(-0.675,0) 2(0.675,0)
  silkscreen extent -1.17,-0.5 1.17,0.5, body extent -0.8,-0.48 0.8,0.48, height 0.8
JS202011SCQN [mm] "Slide Switches - DPDT, SMD, ON-ON"
  rect 1.2x2.5 smd: 1(-2.5,-2.75) 2(0,-2.75) 3(2.5,-2.75) 4(-2.5,2.75) 5(0,2.75) 6(2.5,2.75)
  silkscreen extent -4.5,-1.8 4.5,1.8, body extent -4.52,-3.75 4.52,3.75, height 5.5
LED_0603_G [mil] "SMD Super Bright LED, GREEN"
  rect 30x32 smd: 1(-27.5,0) 2(27.5,0)
  silkscreen extent -58,-20 48,20, body extent -32,-16 32,16, height 24
LED_DUAL_0606 [mm]
  rect 0.65x0.85 smd paste+0: 1(0.425,0.725) 2(-0.425,0.725) 3(0.425,-0.725) 4(-0.425,-0.725)
  silkscreen extent -0.75,-0.8 0.75,0.8, body extent -0.75,-0.8 0.75,0.8, height 0.55
LIST_1x6_SMD [mm] "Pin List, 2.54mm, SMD"
  rect 1.02x2.19 smd: 1(0,-1.465) 1(0,1.465) 2(2.54,-1.465) 2(2.54,1.465) 3(5.08,-1.465) 3(5.08,1.465) 4(7.62,-1.465) 4(7.62,1.465) 5(10.16,-1.465) 5(10.16,1.465) 6(12.7,-1.465) 6(12.7,1.465)
  silkscreen extent -1.27,-1.27 13.97,1.27
LIST_1x8_SMD [mm] "Pin List, 2.54mm, SMD"
  rect 1.02x2.19 smd: 1(0,-1.465) 1(0,1.465) 2(2.54,-1.465) 2(2.54,1.465) 3(5.08,-1.465) 3(5.08,1.465) 4(7.62,-1.465) 4(7.62,1.465) 5(10.16,-1.465) 5(10.16,1.465) 6(12.7,-1.465) 6(12.7,1.465) 7(15.24,-1.465) 7(15.24,1.465) 8(17.78,-1.465) 8(17.78,1.465)
  silkscreen extent -1.27,-1.27 19.05,1.27
LIST_1x9_SMD [mm] "Pin List, 2.54mm, SMD"
  rect 1.02x2.19 smd: 1(0,-1.465) 1(0,1.465) 2(2.54,-1.465) 2(2.54,1.465) 3(5.08,-1.465) 3(5.08,1.465) 4(7.62,-1.465) 4(7.62,1.465) 5(10.16,-1.465) 5(10.16,1.465) 6(12.7,-1.465) 6(12.7,1.465) 7(15.24,-1.465) 7(15.24,1.465) 8(17.78,-1.465) 8(17.78,1.465) 9(20.32,-1.465) 9(20.32,1.465)
  silkscreen extent -1.27,-1.27 21.59,1.27
LIST_1x10_SMD [mm] "Pin List, 2.54mm, SMD"
  rect 1.02x2.19 smd: 1(0,-1.465) 1(0,1.465) 2(2.54,-1.465) 2(2.54,1.465) 3(5.08,-1.465) 3(5.08,1.465) 4(7.62,-1.465) 4(7.62,1.465) 5(10.16,-1.465) 5(10.16,1.465) 6(12.7,-1.465) 6(12.7,1.465) 7(15.24,-1.465) 7(15.24,1.465) 8(17.78,-1.465) 8(17.78,1.465) 9(20.32,-1.465) 9(20.32,1.465) 10(22.86,-1.465) 10(22.86,1.465)
  silkscreen extent -1.27,-1.27 24.13,1.27
LIST_ANG_1x2-SMD-2.54MM [mm] "Pin List, 2.54mm, Surface Mount, Angled"
  round 1.78 hole 1.78: 0(0,-4.496)
  rect 1.27x3.18 smd: 1(-1.27,0) 2(1.27,0)
  silkscreen extent -2.54,-11.58 2.54,-1.8, body extent -2.56,-11.61 2.52,1.35, height 3.03
"Molex 15-91-2060" [mil] "MOLEX - 15-91-2060 - BOARD-BOARD CONN, HEADER, 6WAY, 2ROW"
  rect 50x150 smd: 1(-100,-87.5) 2(-100,87.5) 3(0,-87.5) 4(0,87.5) 5(100,-87.5) 6(100,87.5)
  silkscreen extent -160,-140 150,100, body extent -150,-148 150,148, height 382
"Molex 051281-0594" [mm] "SOT23, 5-Leads, Body 2,90x2,80mm, Pitch 0,95mm, IPC Medium Density"
  rect 0.6x2.6 smd: 0(-0.9,-2.3) 0(2.9,-2.3)
  rect 0.35x0.8 smd: 1(0,0) 2(0.5,0) 3(1,0) 4(1.5,0) 5(2,0)
  silkscreen extent -1.45,-3.85 3.45,0, body extent -1.45,-3.85 3.45,0, height 2.05
NORDIC_LOGO_M [mil] "Medium Nordic Logo"
  silkscreen extent -80,-78 90,80
QFN40P600X600X90-48N [mm] "QFN, 48-Leads, Body 6,0x6,0mm (max), Pitch 0,40mm, IPC Medium Density"
  oval 0.65x0.2 smd: 1(-3.025,2.2) 2(-3.025,1.8) 3(-3.025,1.4) 4(-3.025,1) 5(-3.025,0.6) 6(-3.025,0.2) 7(-3.025,-0.2) 8(-3.025,-0.6) 9(-3.025,-1) 10(-3.025,-1.4) 11(-3.025,-1.8) 12(-3.025,-2.2) 25(3.025,-2.2) 26(3.025,-1.8) 27(3.025,-1.4) 28(3.025,-1) 29(3.025,-0.6) 30(3.025,-0.2) 31(3.025,0.2) 32(3.025,0.6) 33(3.025,1) 34(3.025,1.4) 35(3.025,1.8) 36(3.025,2.2)
  oval 0.2x0.65 smd: 13(-2.2,-3.025) 14(-1.8,-3.025) 15(-1.4,-3.025) 16(-1,-3.025) 17(-0.6,-3.025) 18(-0.2,-3.025) 19(0.2,-3.025) 20(0.6,-3.025) 21(1,-3.025) 22(1.4,-3.025) 23(1.8,-3.025) 24(2.2,-3.025) 37(2.2,3.025) 38(1.8,3.025) 39(1.4,3.025) 40(1,3.025) 41(0.6,3.025) 42(0.2,3.025) 43(-0.2,3.025) 44(-0.6,3.025) 45(-1,3.025) 46(-1.4,3.025) 47(-1.8,3.025) 48(-2.2,3.025)
  rect 4.7x4.7 smd: 49(0,0)
  silkscreen extent -4.02,-3 3,3, body extent -3.02,-3.02 3.02,3.02, height 0.86
RESC1005X04L [mm] "Chip Resistor, 2-Leads, Body 1.0x0.5mm, IPC High Density"
  rect 0.6x0.55 smd: 1(-0.5,0) 2(0.5,0)
  silkscreen extent -0.88,-0.38 0.87,0.37, body extent -0.5,-0.25 0.5,0.25, height 0.3
SOCKET_1x6_SMD [mm] "Socket, 2.54mm, SMD"
  rect 1.02x2.19 smd: 1(0,-1.465) 1(0,1.465) 2(2.54,-1.465) 2(2.54,1.465) 3(5.08,-1.465) 3(5.08,1.465) 4(7.62,-1.465) 4(7.62,1.465) 5(10.16,-1.465) 5(10.16,1.465) 6(12.7,1.465) 6(12.7,-1.465)
  silkscreen extent -1.27,-1.27 13.97,1.27, body extent -1.27,-2.29 13.97,2.29, height 7.47
SOCKET_1x8_SMD [mm] "Socket, 2.54mm, SMD"
  rect 1.02x2.19 smd: 1(0,-1.465) 1(0,1.465) 2(2.54,-1.465) 2(2.54,1.465) 3(5.08,-1.465) 3(5.08,1.465) 4(7.62,-1.465) 4(7.62,1.465) 5(10.16,-1.465) 5(10.16,1.465) 6(12.7,1.465) 6(12.7,-1.465) 7(15.24,-1.465) 7(15.24,1.465) 8(17.78,-1.465) 8(17.78,1.465)
  silkscreen extent -1.27,-1.27 19.05,1.27, body extent -1.27,-2.29 19.05,2.29, height 7.47
SOCKET_1x9_SMD [mm] "Socket, 2.54mm, SMD"
  rect 1.02x2.19 smd: 1(0,1.465) 1(0,-1.465) 2(2.54,-1.465) 2(2.54,1.465) 3(5.08,-1.465) 3(5.08,1.465) 4(7.62,-1.465) 4(7.62,1.465) 5(10.16,-1.465) 5(10.16,1.465) 6(12.7,1.465) 6(12.7,-1.465) 7(15.24,-1.465) 7(15.24,1.465) 8(17.78,-1.465) 8(17.78,1.465) 9(20.32,-1.465) 9(20.32,1.465)
  silkscreen extent -1.27,-1.27 21.59,1.27, body extent -1.26,-2.3 21.6,2.28, height 7.47
SOCKET_1x10_SMD [mm] "Socket, 2.54mm, SMD"
  rect 1.02x2.19 smd: 1(0,1.465) 1(0,-1.465) 2(2.54,-1.465) 2(2.54,1.465) 3(5.08,-1.465) 3(5.08,1.465) 4(7.62,-1.465) 4(7.62,1.465) 5(10.16,-1.465) 5(10.16,1.465) 6(12.7,-1.465) 6(12.7,1.465) 7(15.24,-1.465) 7(15.24,1.465) 8(17.78,-1.465) 8(17.78,1.465) 9(20.32,-1.465) 9(20.32,1.465) 10(22.86,-1.465) 10(22.86,1.465)
  silkscreen extent -1.27,-1.27 24.13,1.27, body extent -1.27,-2.29 24.13,2.29, height 7.47
SOCKET_2x3_SMD-2.54mm-bottom [mm] "Socket, 2.54mm, SMD"
  rect 1.02x2.22 smd far side: 1(-2.54,-2.825) 2(-2.54,2.825) 3(0,-2.825) 4(0,2.825) 5(2.54,-2.825) 6(2.54,2.825)
SOD-523 [mm]
  rect 0.4x0.5 smd: 1(0.7,0) 3(-0.7,0)
  silkscreen extent -0.6,-0.4 0.6,0.4, body extent -0.8,-0.4 0.8,0.4, height 0.7
Solderbridge#1 [mm]
  round 0.2 smd paste-10: 1(0,0) 2(0.625,0)
  Top Layer region: 0.389,0.432 0.465,0.505 0.583,0.467 0.648,0.424 0.721,0.351 0.775,0.292 0.833,0.193 0.861,0.099 0.856,-0.122 0.831,-0.193 0.747,-0.33 0.663,-0.411 0.571,-0.469 0.47,-0.5 0.419,-0.483 0.389,-0.43
  Top Layer region: 0.236,-0.432 0.16,-0.505 0.042,-0.467 -0.023,-0.424 -0.097,-0.351 -0.15,-0.292 -0.208,-0.193 -0.236,-0.099 -0.231,0.122 -0.206,0.193 -0.122,0.33 -0.038,0.411 0.054,0.469 0.155,0.5 0.206,0.483 0.236,0.43
  Top Layer lines w0.152: 0.159,0.431 ccw(c0.27,0) 0.159,-0.431 ; 0.465,0.431 cw(c0.355,0) 0.465,-0.431
Solderbridge#2 [mm]
  round 0.2 smd paste-10: 1(0,0) 2(0.625,0)
  Top Layer region: 0.389,0.432 0.465,0.505 0.583,0.467 0.648,0.424 0.721,0.351 0.775,0.292 0.833,0.193 0.861,0.099 0.856,-0.122 0.831,-0.193 0.747,-0.33 0.663,-0.411 0.571,-0.469 0.47,-0.5 0.419,-0.483 0.389,-0.43
  Top Layer region: 0.236,-0.432 0.16,-0.505 0.042,-0.467 -0.023,-0.424 -0.097,-0.351 -0.15,-0.292 -0.208,-0.193 -0.236,-0.099 -0.231,0.122 -0.206,0.193 -0.122,0.33 -0.038,0.411 0.054,0.469 0.155,0.5 0.206,0.483 0.236,0.43
  Top Layer lines w0.152: 0.465,-0.431 ccw(c0.355,0) 0.774,0.149 ccw(c0.355,0) 0.465,0.431 ; 0.159,-0.431 cw(c0.27,0) -0.175,0 cw(c0.27,0) 0.025,0.371 cw(c0.27,0) 0.159,0.431
Solderbridge#3 [mm]
  round 0.2 smd paste-10: 1(0,0) 2(0.625,0)
  Top Layer region: 0.236,-0.432 0.16,-0.505 0.042,-0.467 -0.023,-0.424 -0.097,-0.351 -0.15,-0.292 -0.208,-0.193 -0.236,-0.099 -0.231,0.122 -0.206,0.193 -0.122,0.33 -0.038,0.411 0.054,0.469 0.155,0.5 0.206,0.483 0.236,0.43
  Top Layer region: 0.389,0.432 0.465,0.505 0.583,0.467 0.648,0.424 0.721,0.351 0.775,0.292 0.833,0.193 0.861,0.099 0.856,-0.122 0.831,-0.193 0.747,-0.33 0.663,-0.411 0.571,-0.469 0.47,-0.5 0.419,-0.483 0.389,-0.43
  Top Layer lines w0.152: 0.465,-0.431 ccw(c0.355,0) 0.799,0 ccw(c0.355,0) 0.465,0.431 ; 0.159,-0.431 cw(c0.27,0) 0.004,-0.356 cw(c0.27,0) 0.159,0.431
Solderbridge_Shorted [mm]
  round 0.2 smd paste-10: 1(0,0) 2(0.676,0)
  Top Layer region: 0.44,0.432 0.516,0.505 0.634,0.467 0.699,0.424 0.772,0.351 0.826,0.292 0.884,0.193 0.912,0.099 0.907,-0.122 0.881,-0.193 0.798,-0.33 0.714,-0.411 0.622,-0.469 0.521,-0.5 0.47,-0.483 0.44,-0.43
  Top Layer region: 0.236,-0.432 0.16,-0.505 0.042,-0.467 -0.023,-0.424 -0.097,-0.351 -0.15,-0.292 -0.208,-0.193 -0.236,-0.099 -0.231,0.122 -0.206,0.193 -0.122,0.33 -0.038,0.411 0.054,0.469 0.155,0.5 0.206,0.483 0.236,0.43
  Top Layer lines w0.152: 0.159,0.431 ccw(c0.27,0) 0.159,-0.431 ; 0.516,0.431 cw(c0.406,0) 0.516,-0.431
  Top Layer lines w0.203: 0,0 0.676,0
SOT65P210X100-6N [mm] "SOT23, 6-Leads, Body 2,2x2,4mm (max), Pitch 0,65mm, IPC Medium Density"
  rect 0.9x0.35 smd: 1(-0.95,0.65) 2(-0.95,0) 3(-0.95,-0.65) 4(0.95,-0.65) 5(0.95,0) 6(0.95,0.65)
  silkscreen extent -1.08,-1.1 0.1,1.5, body extent -1.05,-1 1.05,1, height 0.92
SOT190P230X110-4L [mm] "SOT143, 4-Leads, Body 3.0x2.5mm (max), Pitch 1.90mm, IPC High Density"
  rect 0.85x1 smd: 1(-1.025,0.75)
  rect 0.85x0.6 smd: 2(-1.025,-0.95) 3(1.025,-0.95) 4(1.025,0.95)
  silkscreen extent -1.15,-1.5 0.7,1.93, body extent -1.21,-1.46 1.21,1.46, height 1
SOT-23A [mil] "SOT-23 footprint"
  rect 30x40 smd: 1(0,0) 2(74.8,0) 3(37.4,82.68)
  silkscreen extent -39,-4 94,79, body extent -20,-5 95,87, height 39
SOT-363 [mm] "SOT-363 (SC88)"
  rect 0.3x0.7 smd: 1(0,0) 2(0.65,0) 3(1.3,0) 4(1.3,1.6) 5(0.65,1.6) 6(0,1.6)
  silkscreen extent -0.82,-0.27 1.65,1.4, body extent -0.35,-0.25 1.65,1.85, height 0.93
TC2050-IDC-NLFP [mil]
  round 39 hole 39 unplated: 0(-150,0) 0(150,-40) 0(150,40)
  round 31 smd paste-196.85: 1(-100,-25) 2(-50,-25) 3(0,-25) 4(50,-25) 5(100,-25) 6(100,25) 7(50,25) 8(0,25) 9(-50,25) 10(-100,25)
  Top Layer pour cut-out: -100,25 -100,-25 100,-25 100,25
TESTPAD-TH [mm]
  round 1.5 hole 1: 1(0,0)
  silkscreen extent -1,-1 1,1
TP_SMD_Ø1.0mm [mm]
  round 1 smd paste-5: 1(0,0)
  silkscreen extent -0.7,-0.7 0.7,0.7
TSQFP50P1600X1600X160-100N [mm] "TSQFP, 100-Leads, Body 16,0x16,0mm (max), Pitch 0,50mm, IPC Medium Density"
  oval 1.65x0.3 smd: 1(-7.575,6) 2(-7.575,5.5) 3(-7.575,5) 4(-7.575,4.5) 5(-7.575,4) 6(-7.575,3.5) 7(-7.575,3) 8(-7.575,2.5) 9(-7.575,2) 10(-7.575,1.5) 11(-7.575,1) 12(-7.575,0.5) 13(-7.575,0) 14(-7.575,-0.5) 15(-7.575,-1) 16(-7.575,-1.5) 17(-7.575,-2) 18(-7.575,-2.5) 19(-7.575,-3) 20(-7.575,-3.5) 21(-7.575,-4) 22(-7.575,-4.5) 23(-7.575,-5) 24(-7.575,-5.5) 25(-7.575,-6) 51(7.575,-6) 52(7.575,-5.5) 53(7.575,-5) 54(7.575,-4.5) 55(7.575,-4) 56(7.575,-3.5) 57(7.575,-3) 58(7.575,-2.5) 59(7.575,-2) 60(7.575,-1.5) 61(7.575,-1) 62(7.575,-0.5) 63(7.575,0) 64(7.575,0.5) 65(7.575,1) 66(7.575,1.5) 67(7.575,2) 68(7.575,2.5) 69(7.575,3) 70(7.575,3.5) 71(7.575,4) 72(7.575,4.5) 73(7.575,5) 74(7.575,5.5) 75(7.575,6)
  oval 0.3x1.65 smd: 26(-6,-7.575) 27(-5.5,-7.575) 28(-5,-7.575) 29(-4.5,-7.575) 30(-4,-7.575) 31(-3.5,-7.575) 32(-3,-7.575) 33(-2.5,-7.575) 34(-2,-7.575) 35(-1.5,-7.575) 36(-1,-7.575) 37(-0.5,-7.575) 38(0,-7.575) 39(0.5,-7.575) 40(1,-7.575) 41(1.5,-7.575) 42(2,-7.575) 43(2.5,-7.575) 44(3,-7.575) 45(3.5,-7.575) 46(4,-7.575) 47(4.5,-7.575) 48(5,-7.575) 49(5.5,-7.575) 50(6,-7.575) 76(6,7.575) 77(5.5,7.575) 78(5,7.575) 79(4.5,7.575) 80(4,7.575) 81(3.5,7.575) 82(3,7.575) 83(2.5,7.575) 84(2,7.575) 85(1.5,7.575) 86(1,7.575) 87(0.5,7.575) 88(0,7.575) 89(-0.5,7.575) 90(-1,7.575) 91(-1.5,7.575) 92(-2,7.575) 93(-2.5,7.575) 94(-3,7.575) 95(-3.5,7.575) 96(-4,7.575) 97(-4.5,7.575) 98(-5,7.575) 99(-5.5,7.575) 100(-6,7.575)
  silkscreen extent -7.7,-6.35 6.35,6.82, body extent -8,-8 8,8, height 1.6
XQFN40P180X260X50-16N [mm] "QFN, 16-Leads, Body 1.80x2.60mm, Pitch 0.40mm, IPC Medium Density"
  oval 0.65x0.22 smd paste-0.02 mask+0.062: 1(-0.825,0.6) 2(-0.825,0.2) 3(-0.825,-0.2) 4(-0.825,-0.6) 9(0.825,-0.6) 10(0.825,-0.2) 11(0.825,0.2) 12(0.825,0.6)
  oval 0.22x0.65 smd paste-0.02 mask+0.062: 5(-0.6,-1.225) 6(-0.2,-1.225) 7(0.2,-1.225) 8(0.6,-1.225) 13(0.6,1.225) 14(0.2,1.225) 15(-0.2,1.225) 16(-0.6,1.225)
  silkscreen extent -1.45,-1.4 1,1.4, body extent -0.91,-1.31 0.91,1.31, height 0.55
XTAL_3215 [mm] "XTAL SMD 3.2 x 1.5 mm"
  rect 1x1.8 smd: 1(-1.25,0) 2(1.25,0)
  silkscreen extent -0.6,-0.75 0.6,0.75, body extent -1.6,-0.75 1.6,0.75, height 0.81

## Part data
Bat1: library part "Bat Holder CR2032 SMD", "Bat Holder CR2032 SMD"
C1 C2 C11 C12: library part C0402-12p, "Capacitor, NP0, ±2%"
C3: library part C0402-0.8p, "Capacitor, NP0, ±5%"
C4 C5 C8 C18 C19 C21 C24 C25 C26 C27 C28 C29 C32 C34 C35 C36 C38 C39 C40 C41 C44 C45 C46 C47: library part C0402-100n, "Capacitor, X7R, ±10%"
C6 C13: library part C0402-N.C., "Not mounted"
C7: library part C0402-100p, "Capacitor, NP0, ±5%"
C9: library part C0603-4µ7, "Capacitor, X5R, ±10%"
C10 C16 C17: library part C0603-1µ0, "Capacitor, X7R, ±10%"
C15: library part C0402-1.2p, "Capacitor, NP0, ±0.1pF"
C20 C31 C33: library part C0603-10µ, "Capacitor, X5R, ±20%"
C22 C23: library part C0402-18p, "Capacitor, NP0, ±5%"
C30: library part C0402-10n, "Capacitor, X7R, ±10%"
C37: library part C0402-10p, "Capacitor, NP0, ±2%"
C42 C43: library part C0402-300p, "Capacitor, NP0, ±5%"
C48 C49 C50 C51: library part C0402-1µ0, "Capacitor, X5R, ±5%"
D1: "Surface Mount Schottky Barrier Diode Array"
D2: "Ultra low capacitance double rail-to-rail ESD protection diode"
D3 D4 D5 D6: "Diode Schottky Vf=0.38, Vr=40V, If=200mA, Ir=500nA"
Fid1 Fid2: library part Fid-Mark, "Fiducial Mark"
J1: "Coaxial Connector with Switch"
J2: library part "FCI 10118193-0001LF", "MicroUSB-B-SMT"
J3: library part TC2050-IDC-NLFP, "CBL PLUG-OF-NAILS 10-PIN"
L1: library part L0402-3n9, "Inductor, 170mA, ±0.1nH"
L2: library part L0603-10µ, "Inductor, 80mA, ±10%"
L3: library part L0402-15n, "Inductor, 320mA, ±5%"
LD5: "Ultra bright AlInGaP Bi-Color LED"
LED1 LED2 LED3 LED4: library part EL19-21SYGC, "LED 0603, EL19-21SYGC"
LOGO1: "Nordic Logo, medium size"
P1 P3: library part "Socket 1x8 SMD", "Socket 1x8, 2.54mm (100mil), SMD"
P2: library part "Socket 1x6 SMD", "Socket 1x6, 2.54mm (100mil), SMD"
P4: library part "Socket 1x10 SMD", "Socket 1x10, 2.54mm (100mil), SMD"
P5: library part "Pin Header 2x3 SMD", "Pin Header 2x3, 2.54mm (100mil) SMD"
P6: library part "Socket 1x9 SMD", "Socket 1x9, 2.54mm (100mil), SMD"
P7 P9 P20: library part "Pin List 1x8 SMD", "Pin List 1x8, 2.54mm (100mil), SMD"
P8: library part "Pin List 1x6 SMD", "Pin List 1x6, 2.54mm (100mil), SMD"
P10: library part "Pin List 1x10 SMD", "Pin List 1x10, 2.54mm (100mil), SMD"
P11: library part "Socket 2x3 SMD Bottom", "Socket 2x3, 2.54mm (100mil), SMD"
P12: library part "Pin List 1x9 SMD", "Pin List 1x9, 2.54mm (100mil), SMD"
P13 P15: "Pin Header 2x8, 2.54mm (100mil)"
P14: "Pin Header 2x6, 2.54mm (100mil)"
P16: "Pin Header 2x10, 2.54mm (100mil)"
P17: "Pin Header 2x9, 2.54mm (100mil)"
P18 P19: library part "Samtec FTSH-105 Keying Shroud", "CONN HEADER 10POS DUAL .05\" SMD KEYING SHROUD"
P21 P22: library part "Pin List Ang 1x2 SMD, 2.54mm", "Pin List 1x2, 2.54mm (100mil), Right Angled, SMD"
P23: "CONN FFC FPC 5POS 0.50MM R/A"
Q1 Q2: library part FDG6321C_IPC, "Fairchild, FDG6321C, Dual N & P Channel Digital FET"
R1 R2 R3 R4 R19 R20: library part R0402-220, "Resistor, ±1%, 0.063W"
R5 R8 R9 R10 R11 R12: library part R0402-10k, "Resistor, ±1%, 0.063W"
R6 R27 R28 R37: library part R0402-N.C., "Not mounted"
R7: library part R0402-47k, "Resistor, ±1%, 0.063W"
R13 R14: library part R0402-39R, "Resistor, ±1%, 0.063W"
R15 R16: library part R0402-150, "Resistor, ±1%, 0.063W"
R17: library part R0402-6k8, "Resistor, ±1%, 0.063W"
R18: library part R0402-1k0, "Resistor, ±1%, 0.063W"
R21 R22 R23 R24 R29 R30: library part R0402-4k7, "Resistor, ±1%, 0.063W"
R25 R26 R38: library part R0402-0R, "Resistor, ±5%, 0.063W"
R31 R32: library part R0402-12k, "Resistor, ±1%, 0.063W"
R33 R34 R35 R36: library part R0402-100k, "Resistor, ±1%, 0.063W"
R39: library part R0402-1M0, "Resistor, ±1%, 0.063W"
R40 R41 R42 R43: library part R0402-18k, "Resistor, ±1%, 0.063W"
SB1 SB2 SB5 SB6 SB7 SB8 SB9 SB13 SB14 SB15 SB16 SB19 SB20 SB21 SB22 SB23 SB24 SB25 SB26 SB27 SB29 SB30: library part "Solderbridge Shorted", "Shorted Solderbridge"
SW1 SW2 SW3: library part ALPS_SKHUALE010, "ALPS - SKHUALE010 - TACTILE SWITCH, SPNO, SMD, 6.5x6.2x2.5mm"
SW4 SW5: library part ALPS_SKHUALE010, "ALPS - SKHUALE010 - Tactile Switch, SPNO, SMD, 6.5x6.2x2.5mm"
SW6: library part JS202011SCQN, "SMD slide Switch (ON-ON)"
TP1 TP2 TP3 TP4 TP5 TP6 TP7 TP8 TP9 TP10 TP11 TP14 TP15: library part TP_SMD_Ø1.0MM, "1.0mm circular SMD testpad"
TP12 TP13: library part "Testpoint TH", "Testpoint, through hole"
U1: "Multi-protocol Bluetooth Low Energy and 2.4GHz proprietary system-on-chip"
U2: "IC MCU 32bit 128kB flash 100LQFP"
U3: "300mA, Low Quiescent Current, Fast Transient Low Dropout Linear Regulator"
U4 U5 U6: library part NX3DV2567GU, "Low-ohmic four-pole double-throw analog switch"
U7: library part PCAL6408AHK, "8-bit I2C-bus I/O expander with interrupt output"
X1: library part XTAL_SMD2016_32MHz_8pF_Epson, "XTAL SMD 2016, 32MHz, Cl=8pF, Tol: ±10ppm, Stab: ±10ppm"
X2: library part "XTAL_FC-135 32.768k", "EPSON TOYOCOM - FC-135 32.768KHZ ±20PPM,9.0PF - CRYSTAL, SM, WATCH"
X3: library part "XTAL SMD 12MHz (3225)", "XTAL SMD 3225, 12MHz, 18pF, ±30ppm"

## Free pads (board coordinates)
  round 126 hole 126: 1(550,299.6) 1(600,2199.6) 1(2600,499.6) 1(2600,1599.6) 1(3800,299.6)

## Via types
v1: diameter 24, hole 12, Top Layer to Bottom Layer, tented both sides, 576 vias
v2: diameter 24, hole 12, Top Layer to Bottom Layer, 21 vias
v3: diameter 25.98, hole 12.99, Top Layer to Bottom Layer, tented both sides, 16 vias

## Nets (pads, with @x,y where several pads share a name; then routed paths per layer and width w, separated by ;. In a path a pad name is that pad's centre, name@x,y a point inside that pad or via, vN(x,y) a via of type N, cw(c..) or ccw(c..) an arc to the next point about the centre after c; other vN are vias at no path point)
ANT: C15.1 J1.3 | length 895.1
  Top Layer w50: 3715.87,1248.16 3900.48,1248.16 3961.87,1186.77 3961.87,563.09
BOOT: R5.1 SW5.1 U2.24 | length 1169.7
  Top Layer w6: SW5.1@721.13,396.34 986.87,396.34 1023.13,432.6 1449.6,432.6 v1(1533,516) ; U2.24@1489.14,801.37 1489.14,772.46 1525,736.6 R5.1@1533.32,736.6 ; v1(1533,708) R5.1@1533,736.28
  Bottom Layer w6: v1(1533,516) v1(1533,708)
BUTTON1: SW1.1 U4.16 | length 460.8
  Top Layer w6: SW1.1@2909.13,666.82 3174.87,666.82 3194.69,647 3242.66,647 3308.12,581.54 U4.16@3308.12,555.07
BUTTON1_EXT: C48.1 D3.3 R40.1 U7.2 | length 533
  Top Layer w6: C48.1@2104.9,1570.77 2104.9,1604.77 R40.1@2105.68,1604.77 ; D3.3@2113.78,1641.77 2105.68,1633.67 R40.1@2105.68,1604.77 ; U7.2@2162.42,1812.13 2179.73,1812.13 2190.24,1801.62 2278.99,1801.62 2297.62,1782.99 2297.62,1706.54 2251.85,1660.77 2161.68,1660.77 R40.1@2105.68,1604.77
BUTTON2: SW2.1 U4.4 | length 484.8
  Top Layer w6: v1(3222.66,591) 3236.04,577.62 U4.4@3236.04,564.48 ; v1(3279.13,667.26) 3614.53,667.26 SW2.1@3614.87,666.92
  Bottom Layer w6: v1(3222.66,591) 3252,591 3279.13,618.13 v1(3279.13,667.26)
BUTTON2_EXT: C49.2 D4.3 R41.1 U7.3 | length 706.9
  Top Layer w6: C49.2@2104.76,1461.77 R41.1@2104.76,1495.77 ; D4.3@2113.86,1532.77 2104.76,1523.67 R41.1@2104.76,1495.77 ; U7.3@2162.42,1827.87 2174.49,1827.87 2190.24,1843.62 2279.77,1843.62 2321.62,1801.77 2321.62,1696.6 2261.79,1636.77 2172.45,1636.77 2143.31,1607.63 2143.31,1532.77 2106.31,1495.77 R41.1@2104.76,1495.77
BUTTON3: SW3.1 U4.8 | length 419.2
  Top Layer w6: SW3.1@2909.02,377.19 SW3.1@3174.77,377.19 ; v1(3177.66,494) 3192.04,508.38 U4.8@3211.44,508.38 ; SW3.1@3178.02,380.44 v1(3178.02,419.63)
  Bottom Layer w6: v1(3177.66,494) 3177.66,419.98 v1(3178.02,419.63)
BUTTON3_EXT: C50.2 D5.3 R42.1 U7.4 | length 681.9
  Top Layer w6: U7.4@2162.42,1843.62 2172.94,1843.62 2177.94,1848.62 2177.94,1873.32 2190.24,1885.62 2279.77,1885.62 2345.62,1819.77 2345.62,1686.66 2260.31,1601.34 2260.31,1514.15 R42.1@2277.99,1496.47 ; C50.2@2277.99,1462.47 R42.1@2277.99,1496.47 ; D5.3@2285.86,1532.77 2277.99,1524.9 R42.1@2277.99,1496.47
